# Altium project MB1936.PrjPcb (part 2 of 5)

## Sheet FDCAN.SchDoc: FDCAN
size A4; Date: Not used; ApprovedBy: Not used; CheckedBy: Not used; Author: Not used; CompanyName: STMicroelectronics; DrawnBy: Not used; Engineer: Not used; Organization: Not used; Address1: Not used; Address2: Not used; Address3: Not used; Address4: Not used; DocumentNumber: Not used; Revision: Not used; SheetNumber: 10; SheetTotal: 18
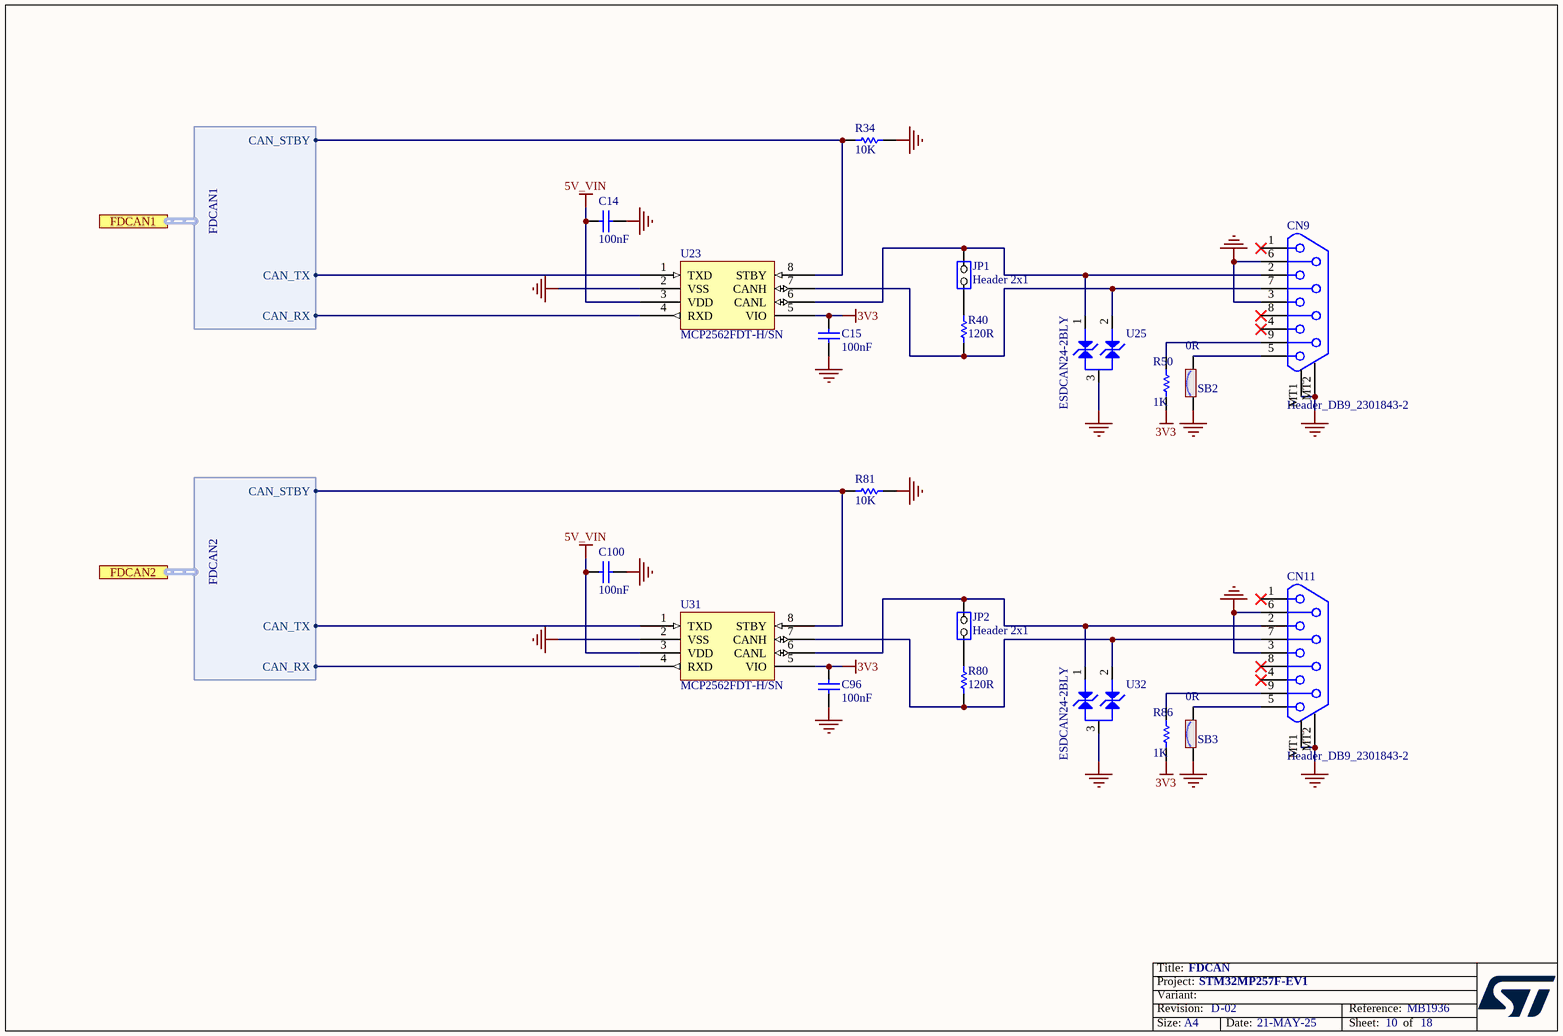
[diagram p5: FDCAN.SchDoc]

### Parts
C14  value 100nF  [C0402]  (hidden comment: Capacitor)
C15  value 100nF  [C0402]  (hidden comment: Capacitor)
C96  value 100nF  [C0402]  (hidden comment: Capacitor)
C100  value 100nF  [C0402]  (hidden comment: Capacitor)
CN9  value Header_DB9_2301843-2  [CON_DB9-MALE_TYCO_2301843-2]  (hidden comment: DB9_Header_male_2301843-2)
CN11  value Header_DB9_2301843-2  [CON_DB9-MALE_TYCO_2301843-2]  (hidden comment: DB9_Header_male_2301843-2)
JP1  value Header 2x1  [CON_SAMTEC_TSW-102-07-G-S]  (hidden comment: Jumper_Header 2x1)
JP2  value Header 2x1  [CON_SAMTEC_TSW-102-07-G-S]  (hidden comment: Jumper_Header 2x1)
R34  value 10K  [R0402]  (hidden comment: Resistor)
R40  value 120R  [R0402]  (hidden comment: Resistor)
R50  value 1K  [R0402]  (hidden comment: Resistor)
R80  value 120R  [R0402]  (hidden comment: Resistor)
R81  value 10K  [R0402]  (hidden comment: Resistor)
R86  value 1K  [R0402]  (hidden comment: Resistor)
SB2  value 0R  [SOLDER-BRIDGE_R0402-0R]  (hidden comment: SB_ON)
SB3  value 0R  [SOLDER-BRIDGE_R0402-0R]  (hidden comment: SB_ON)
U23  value MCP2562FDT-H/SN  [ICC_SO8_5X4_P127]  (hidden comment: MCP2562FD)
U25  value ESDCAN24-2BLY  [ESD_SOT23]  (hidden comment: ESD-TRANSIL-DUAL-BIDIR)
U31  value MCP2562FDT-H/SN  [ICC_SO8_5X4_P127]  (hidden comment: MCP2562FD)
U32  value ESDCAN24-2BLY  [ESD_SOT23]  (hidden comment: ESD-TRANSIL-DUAL-BIDIR)

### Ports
FDCAN1 (harness FDCAN1), FDCAN2 (harness FDCAN2)

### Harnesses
FDCAN1: CAN_TX, CAN_RX, CAN_STBY
FDCAN2: CAN_TX, CAN_RX, CAN_STBY

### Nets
3V3: C15.2 C96.2 R50.1 R86.1 U23.5(VIO) U31.5(VIO)
5V_VIN: C14.1 C100.1 U23.3(VDD) U31.3(VDD)
GND: C14.2 C15.1 C96.1 C100.2 CN9.3 CN9.6 CN9.MT1 CN9.MT2 CN11.3 CN11.6 CN11.MT1 CN11.MT2 R34.2 R81.2 SB2.1 SB3.1 U23.2(VSS) U25.3 U31.2(VSS) U32.3
FDCAN1.RX: U23.4(RXD) ; port FDCAN1.CAN_RX
FDCAN1.STBY: R34.1 U23.8(STBY) ; port FDCAN1.CAN_STBY
FDCAN1.TX: U23.1(TXD) ; port FDCAN1.CAN_TX
FDCAN3.RX: U31.4(RXD) ; port FDCAN2.CAN_RX
FDCAN3.STBY: R81.1 U31.8(STBY) ; port FDCAN2.CAN_STBY
FDCAN3.TX: U31.1(TXD) ; port FDCAN2.CAN_TX
NetCN9_2: CN9.2 JP1.2(NO) U23.6(CANL) U25.1
NetCN9_5: CN9.5 SB2.2
NetCN9_7: CN9.7 R40.1 U23.7(CANH) U25.2
NetCN9_9: CN9.9 R50.2
NetCN11_2: CN11.2 JP2.2(NO) U31.6(CANL) U32.1
NetCN11_5: CN11.5 SB3.2
NetCN11_7: CN11.7 R80.1 U31.7(CANH) U32.2
NetCN11_9: CN11.9 R86.2
NetJP1_1: JP1.1(COMMON) R40.2
NetJP2_1: JP2.1(COMMON) R80.2

Not connected (* = marked no-connect by the designer): CN9 1* 4* 8*; CN11 1* 4* 8*

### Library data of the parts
C14 C15 C96 C100 = MCD-00006: Capacitor, MLCC, 100nF, 16V, X7R, +/-10%, 0402, T=0.5mm; Part_Preference: Recommended; Manufacturer: YAGEO; Manufacturer_Part_Number: CC0402KRX7R7BB104; Partial_Alternate_Internal_Part_Number: MCD-03299; Order_Code_RS: 9402047; Component_Country_Of_Origin: China; ShowFields: YES; ID: 2474
CN9 CN11 = MCD-01978: Connector_DB9-Male, 9pins, 1.39mm, RA, TH, T= 13.575mm/3.8mm; Part_Preference: Recommended; Manufacturer: TE CONNECTIVITY; Partial_Alternate_Internal_Part_Number: MCD-04464; Component_Country_Of_Origin: China; ShowFields: YES; ID: 4078
JP1 JP2 = MCD-00045: Header, 2x1, 2,54mm, VR, TH, Height 5.84mm/2.54mm; Part_Type: Connector; Manufacturer_Part_Number: TSW-102-07-G-S; Manufacturer: SAMTEC; Alternate_Manufacturer_Part_Number: 313102S111116;313102S111116; Alternate_Manufacturer: JIUBABA; LIANYI; Alternate_Internal_Part_Number: MCD-02390; Part_Preference: Recommended; Partial_Alternate_Internal_Part_Number: MCD-02957, MCD-03720, MCD-03979, MCD-04249; Provided_By: SUBCO; Component_Country_Of_Origin: China, Costa Rica, Malaysia, USA, Vietnam; ID: 2545; Order_Code_RS: 2505044; ShowFields: YES
R34 R81 = MCD-00053: Resistor,10K,0402,1%,1/16W; Manufacturer_Part_Number: RC0402FR-0710KL; Manufacturer: YAGEO; BMS_Part_Number: 9131590; Part_Preference: Recommended; Provided_By: SUBCO; Component_Country_Of_Origin: China; ID: 2539; Order_Code_RS: 9239359; ShowFields: YES
R40 R80 = MCD-00194: Resistor, 120R, 0402, +/-1%, 1/16W; Part_Preference: Recommended; Manufacturer: YAGEO; Manufacturer_Part_Number: RC0402FR-07120RL; Component_Country_Of_Origin: China; ShowFields: YES; ID: 2674
R50 R86 = MCD-00061: Resistor,1K,0402,1%,1/16W; Manufacturer_Part_Number: RC0402FR-071KL; Manufacturer: YAGEO; Part_Preference: Recommended; Provided_By: SUBCO; Component_Country_Of_Origin: China; ID: 2532; Order_Code_RS: 9239235; ShowFields: YES
SB2 SB3 = MCD-01618: Solder Bridge 0402 ON; Part_Type: Resistor; Manufacturer_Part_Number: RC0402JR-070RL; Manufacturer: YAGEO; Part_Preference: Recommended; Provided_By: SUBCO; Component_Country_Of_Origin: China; ID: 3718; Order_Code_RS: 618-5804; ShowFields: YES
U23 U31 = MCD-00129: High-Speed CAN Flexible Data Rate Transceiver; Part_Type: IC; Manufacturer: MICROCHIP; Part_Preference: Recommended; Provided_By: SUBCO; Component_Country_Of_Origin: Unknown; ID: 2737; ShowFields: YES
U25 U32 = MCD-00143: Automotive dual-line Transil. ESD CAN; Part_Type: Diode; Manufacturer: STMICROELECTRONICS; BMS_Part_Number: 9179002; Manufacturer_HQ_COO: EU; Part_Preference: Recommended; Provided_By: SUBCO with ST control; Component_Country_Of_Origin: China; ID: 2726; Order_Code_RS: 165-5883; ShowFields: YES

## Sheet Ethernet1.SchDoc: ETHERNET 1
size A3; Date: Not used; ApprovedBy: Not used; CheckedBy: Not used; Author: Not used; CompanyName: STMicroelectronics; DrawnBy: Not used; Engineer: Not used; Organization: Not used; Address1: Not used; Address2: Not used; Address3: Not used; Address4: Not used; DocumentNumber: Not used; Revision: Not used; SheetNumber: 7; SheetTotal: 18
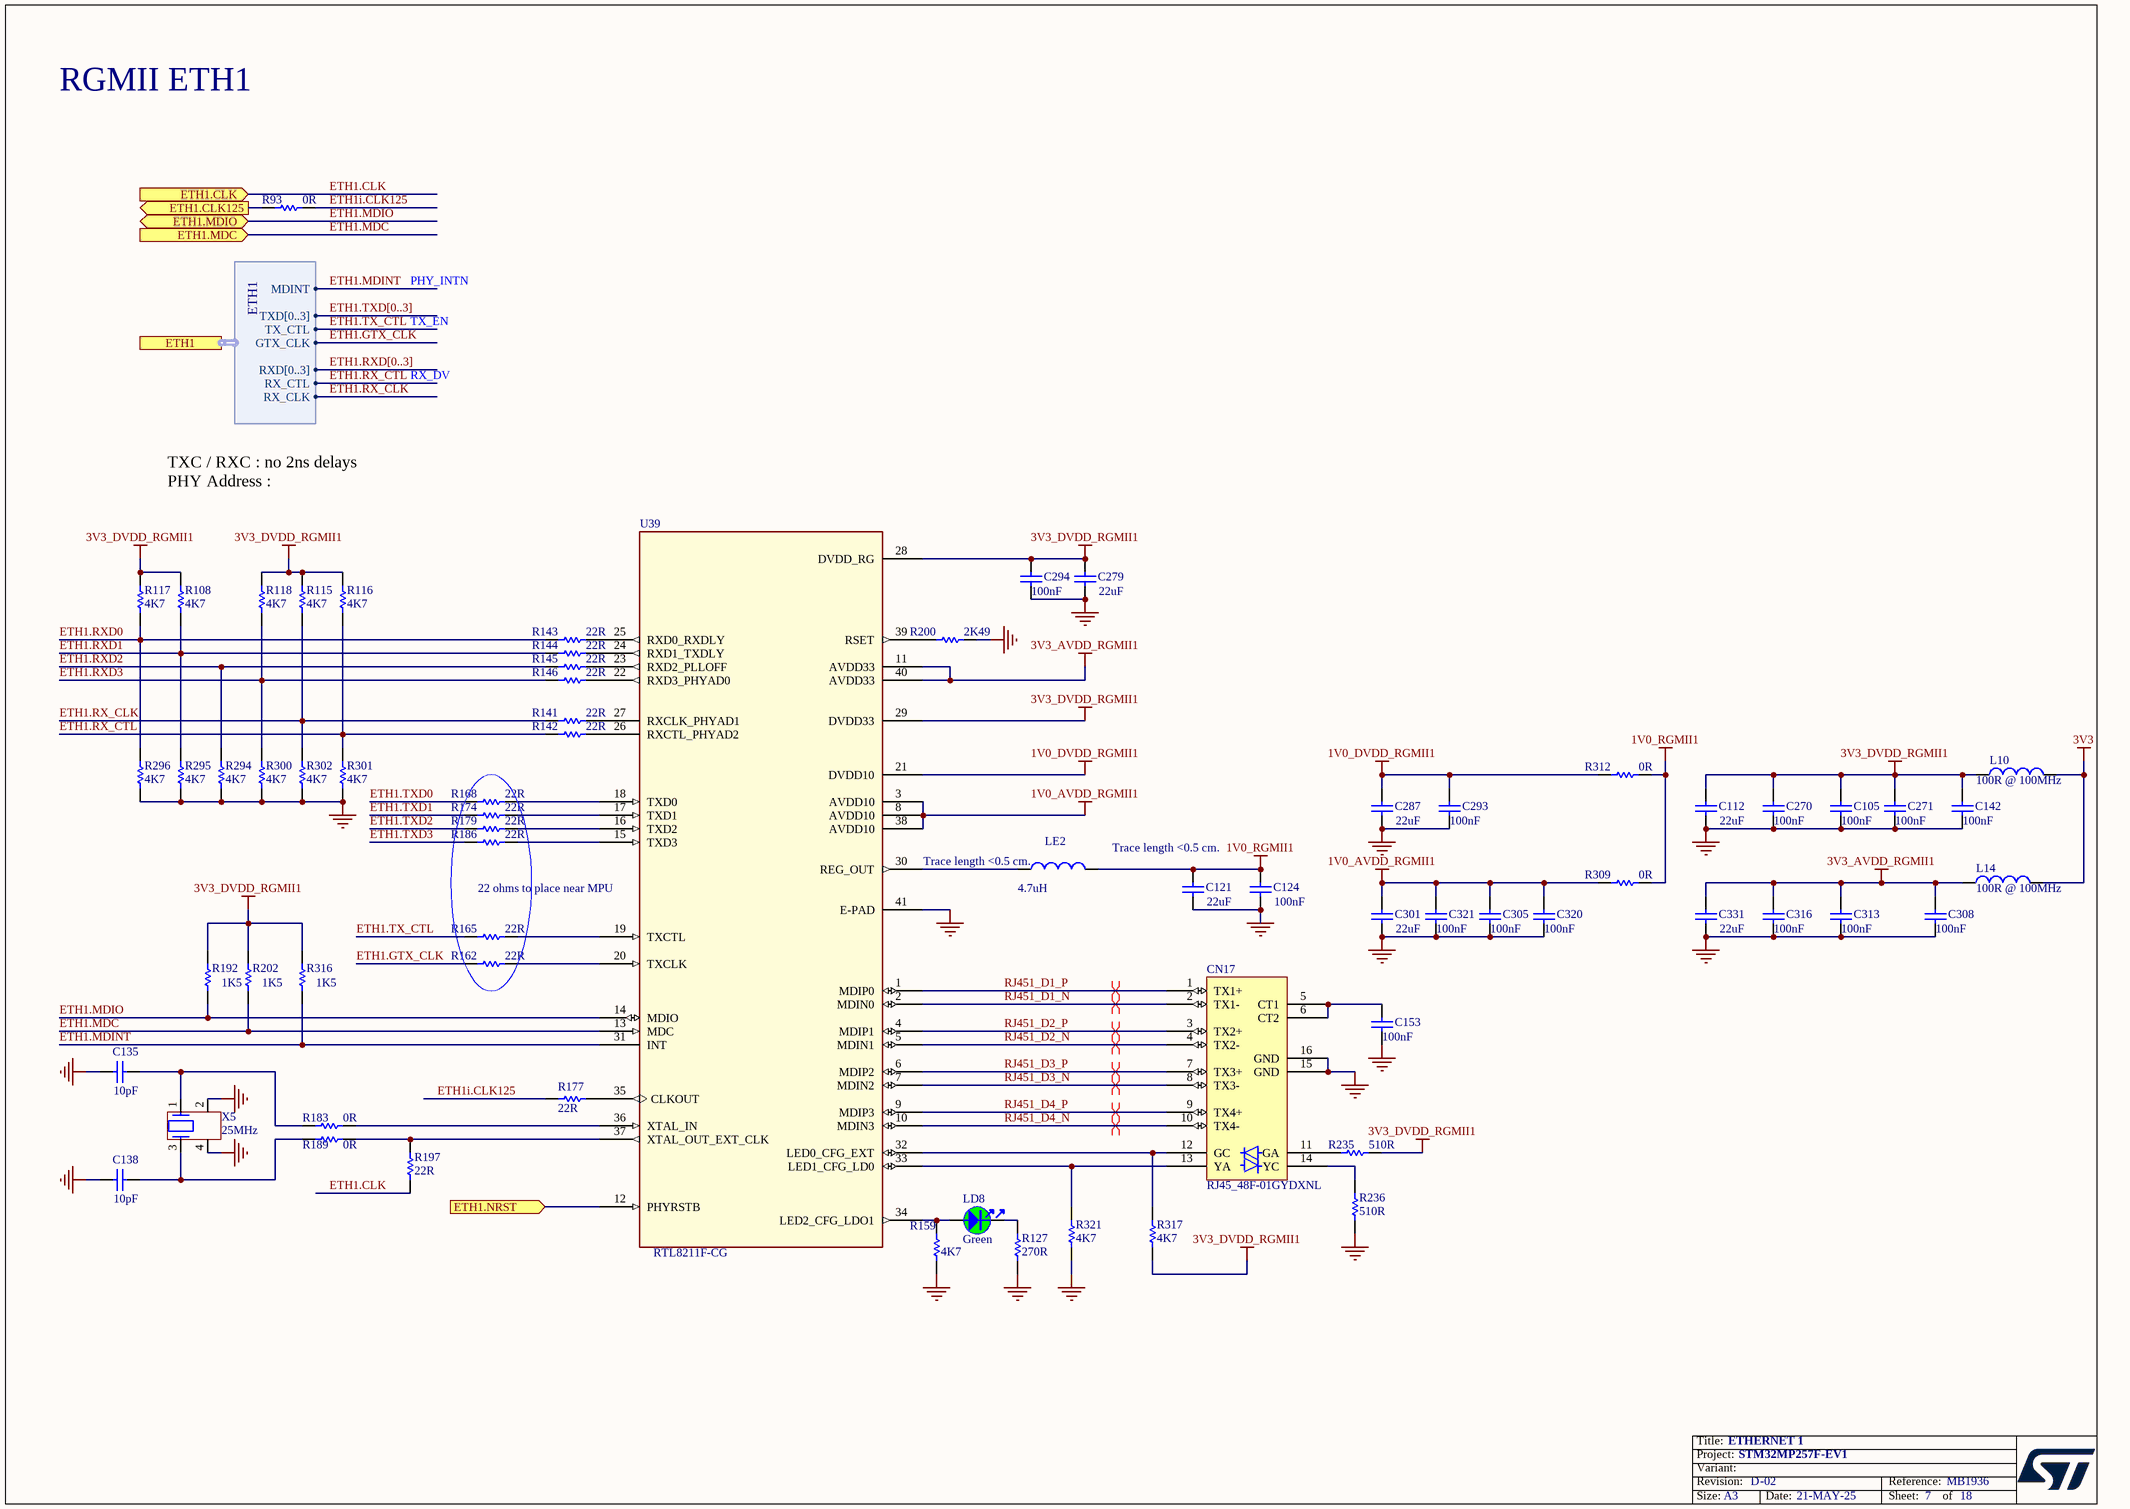
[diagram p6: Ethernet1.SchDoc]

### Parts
C105  value 100nF  [C0402]
C112  value 22uF  [C0603]
C121  value 22uF  [C0603]
C124  value 100nF  [C0402]
C135  value 10pF  [C0402]
C138  value 10pF  [C0402]
C142  value 100nF  [C0402]
C153  value 100nF  [C0402]
C270  value 100nF  [C0402]
C271  value 100nF  [C0402]
C279  value 22uF  [C0603]
C287  value 22uF  [C0603]
C293  value 100nF  [C0402]
C294  value 100nF  [C0402]
C301  value 22uF  [C0603]
C305  value 100nF  [C0402]
C308  value 100nF  [C0402]
C313  value 100nF  [C0402]
C316  value 100nF  [C0402]
C320  value 100nF  [C0402]
C321  value 100nF  [C0402]
C331  value 22uF  [C0603]
CN17  value RJ45_48F-01GYDXNL  [CON_RJ45_YD_48F-01GYDXNL_LED-P]  (hidden comment: ​New part for use of led pulled down on pin 13/14 , schematic more lisible.)
L10  value 100R @ 100MHz  [FIL_0603_H0P65]
L14  value 100R @ 100MHz  [FIL_0603_H0P65]
LD8  value Green  [LED_0603_OSRAM_LG-Q396-PS-35_GREEN_1A2K_H0P4]  (hidden comment: LED_green)
LE2  value 4.7uH  [L1210_LQH]
R93  value 0R  [R0402]
R108  value 4K7  [R0402]
R115  value 4K7  [R0402]
R116  value 4K7  [R0402]
R117  value 4K7  [R0402]
R118  value 4K7  [R0402]
R127  value 270R  [R0402]  (hidden comment: Resistor)
R141  value 22R  [R0201_H0P23]  (hidden comment: Resistor)
R142  value 22R  [R0201_H0P23]  (hidden comment: Resistor)
R143  value 22R  [R0201_H0P23]  (hidden comment: Resistor)
R144  value 22R  [R0201_H0P23]  (hidden comment: Resistor)
R145  value 22R  [R0201_H0P23]  (hidden comment: Resistor)
R146  value 22R  [R0201_H0P23]  (hidden comment: Resistor)
R159  value 4K7  [R0402]
R162  value 22R  [R0201_H0P23]  (hidden comment: Resistor)
R165  value 22R  [R0201_H0P23]  (hidden comment: Resistor)
R168  value 22R  [R0201_H0P23]  (hidden comment: Resistor)
R174  value 22R  [R0201_H0P23]  (hidden comment: Resistor)
R177  value 22R  [R0201_H0P23]  (hidden comment: Resistor)
R179  value 22R  [R0201_H0P23]  (hidden comment: Resistor)
R183  value 0R  [R0402]
R186  value 22R  [R0201_H0P23]  (hidden comment: Resistor)
R189  value 0R  [R0402]
R192  value 1K5  [R0402]
R197  value 22R  [R0201_H0P23]  (hidden comment: Resistor)
R200  value 2K49  [R0402]
R202  value 1K5  [R0402]
R235  value 510R  [R0402]
R236  value 510R  [R0402]
R294  value 4K7  [R0402]
R295  value 4K7  [R0402]
R296  value 4K7  [R0402]
R300  value 4K7  [R0402]
R301  value 4K7  [R0402]
R302  value 4K7  [R0402]
R309  value 0R  [R0603]
R312  value 0R  [R0603]
R316  value 1K5  [R0402]
R317  value 4K7  [R0402]
R321  value 4K7  [R0402]
U39  RTL8211F-CG  [ICC_QFN40-EPAD_5X5_P040]
X5  value 25MHz  [CRY_NX3225HA_4P]  (hidden comment: XTAL_4_PINS)

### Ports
ETH1 (harness ETH1), ETH1.CLK125 (out), ETH1.CLK (in), ETH1.MDC (in), ETH1.MDIO (bidir), ETH1.NRST (in)

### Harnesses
ETH1: MDINT, TXD[0..3], RX_CLK, GTX_CLK, TX_CTL, RXD[0..3], RX_CTL

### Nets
1V0_AVDD_RGMII1: C301.2 C305.2 C320.2 C321.2 R309.1 U39.3(AVDD10) U39.8(AVDD10) U39.38(AVDD10)
1V0_DVDD_RGMII1: C287.2 C293.2 R312.1 U39.21(DVDD10)
1V0_RGMII1: C121.2 C124.2 LE2.2 R309.2 R312.2
3V3: L10.2 L14.2
3V3_AVDD_RGMII1: C308.2 C313.2 C316.2 C331.2 L14.1 U39.11(AVDD33) U39.40(AVDD33)
3V3_DVDD_RGMII1: C105.2 C112.2 C142.2 C270.2 C271.2 C279.1 C294.2 L10.1 R108.2 R115.2 R116.2 R117.2 R118.2 R192.2 R202.2 R235.2 R316.2 R317.1 U39.28(DVDD_RG) U39.29(DVDD33)
GND: C105.1 C112.1 C121.1 C124.1 C135.1 C138.1 C142.1 C153.1 C270.1 C271.1 C279.2 C287.1 C293.1 C294.1 C301.1 C305.1 C308.1 C313.1 C316.1 C320.1 C321.1 C331.1 CN17.15(GND) CN17.16(GND) R127.2 R159.1 R200.2 R236.1 R294.1 R295.1 R296.1 R300.1 R301.1 R302.1 R321.1 U39.41(E-PAD) X5.2 X5.4
ETH1.CLK: R197.1 ; port ETH1.CLK
ETH1.CLK125: R93.1 ; port ETH1.CLK125
ETH1.GTX_CLK: R162.1 ; port ETH1.GTX_CLK
ETH1.MDC: R202.1 U39.13(MDC) ; port ETH1.MDC
ETH1.MDINT: R316.1 U39.31(INT) ; port ETH1.MDINT
ETH1.MDIO: R192.1 U39.14(MDIO) ; port ETH1.MDIO
ETH1.NRST: U39.12(PHYRSTB) ; port ETH1.NRST
ETH1.RX_CLK: R115.1 R141.1 R302.2 ; port ETH1.RX_CLK
ETH1.RX_CTL: R116.1 R142.1 R301.2 ; port ETH1.RX_CTL
ETH1.RXD0: R117.1 R143.1 R296.2
ETH1.RXD1: R108.1 R144.1 R295.2
ETH1.RXD2: R145.1 R294.2
ETH1.RXD3: R118.1 R146.1 R300.2
ETH1.TX_CTL: R165.1 ; port ETH1.TX_CTL
ETH1.TXD0: R168.1
ETH1.TXD1: R174.1
ETH1.TXD2: R179.1
ETH1.TXD3: R186.1
ETH1i.CLK125: R93.2 R177.1
RJ451_D1_N: CN17.2(TX1-) U39.2(MDIN0)
RJ451_D1_P: CN17.1(TX1+) U39.1(MDIP0)
RJ451_D2_N: CN17.4(TX2-) U39.5(MDIN1)
RJ451_D2_P: CN17.3(TX2+) U39.4(MDIP1)
RJ451_D3_N: CN17.8(TX3-) U39.7(MDIN2)
RJ451_D3_P: CN17.7(TX3+) U39.6(MDIP2)
RJ451_D4_N: CN17.10(TX4-) U39.10(MDIN3)
RJ451_D4_P: CN17.9(TX4+) U39.9(MDIP3)
NetC135_2: C135.2 R183.1 X5.1
NetC138_2: C138.2 R189.1 X5.3
NetC153_2: C153.2 CN17.5(CT1) CN17.6(CT2)
NetCN17_11: CN17.11(GA) R235.1
NetCN17_12: CN17.12(GC) R317.2 U39.32(LED0_CFG_EXT)
NetCN17_13: CN17.13(YA) R321.2 U39.33(LED1_CFG_LD0)
NetCN17_14: CN17.14(YC) R236.2
NetLD8_1: LD8.1 R159.2 U39.34(LED2_CFG_LDO1)
NetLD8_2: LD8.2 R127.1
NetLE2_1: LE2.1 U39.30(REG_OUT)
NetR141_2: R141.2 U39.27(RXCLK_PHYAD1)
NetR142_2: R142.2 U39.26(RXCTL_PHYAD2)
NetR143_2: R143.2 U39.25(RXD0_RXDLY)
NetR144_2: R144.2 U39.24(RXD1_TXDLY)
NetR145_2: R145.2 U39.23(RXD2_PLLOFF)
NetR146_2: R146.2 U39.22(RXD3_PHYAD0)
NetR162_2: R162.2 U39.20(TXCLK)
NetR165_2: R165.2 U39.19(TXCTL)
NetR168_2: R168.2 U39.18(TXD0)
NetR174_2: R174.2 U39.17(TXD1)
NetR177_2: R177.2 U39.35(CLKOUT)
NetR179_2: R179.2 U39.16(TXD2)
NetR183_2: R183.2 U39.36(XTAL_IN)
NetR186_2: R186.2 U39.15(TXD3)
NetR189_2: R189.2 R197.2 U39.37(XTAL_OUT_EXT_CLK)
NetR200_1: R200.1 U39.39(RSET)

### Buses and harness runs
bus ETH1.RXD[0..3]
bus ETH1.TXD[0..3]

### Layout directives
differential pair: RJ451_D1_N, RJ451_D1_P, RJ451_D2_N, RJ451_D2_P, RJ451_D3_N, RJ451_D3_P, RJ451_D4_N, RJ451_D4_P

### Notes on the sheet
- RGMII ETH1
- PHY_INTN
- RX_DV
- TX_EN
- TXC / RXC : no 2ns delays
  PHY Address :
  AD[2:0] : 100 (0x04) default
- Trace length <0.5 cm.
- (near U39) 22 ohms to place near MPU
- (near LE2) Trace length <0.5 cm.

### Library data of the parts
C105 C124 C142 C153 C270 C271 C293 C294 C305 C308 C313 C316 C320 C321 = MCD-00006: Capacitor,100nF,16V,X7R,10%,0402; Manufacturer_Part_Number: CC0402KRX7R7BB104; Manufacturer: YAGEO; Alternate_Manufacturer: MURATA; Alternate_Manufacturer_Part_Number: GCM155R71C104KA55D; Part_Preference: Recommended; Partial_Alternate_Internal_Part_Number: MCD-03299; Provided_By: SUBCO; Initial_Board_Reference: mb1274; Order_Code_RS: 9402047; Component_Country_Of_Origin: China; ID: 2474; ShowFields: YES
C112 C121 C279 C287 C301 C331 = MCD-00100: Capacitor,22uF,6V3,X5R,20%,0603; Manufacturer_Part_Number: GRM188R60J226MEA0; Manufacturer: MURATA; Part_Preference: Recommended; Partial_Alternate_Internal_Part_Number: MCD-04184; ECCN_US: EAR99; ECCN_EU: NEC; Provided_By: SUBCO; Initial_Board_Reference: mb1262; Component_Country_Of_Origin: Japan°°; ID: 2766; ShowFields: YES
C135 C138 = MCD-00015: Capacitor,10pF,50V,NPO,5%,0402; Manufacturer_Part_Number: CC0402JRNPO9BN100; Manufacturer: YAGEO; Part_Preference: Recommended; Provided_By: SUBCO; Initial_Board_Reference: mb1274; Order_Code_RS: 3019160RL; Component_Country_Of_Origin: China; ID: 2465; ShowFields: YES
CN17 = MCD-01129: Connector_RJ45, led pull down, T= 13.84mm; Manufacturer_Part_Number: 48F-01GYDXNL; Manufacturer: YUAN DEAN SCIENTIFIC; Part_Preference: Recommended; Partial_Alternate_Internal_Part_Number: MCD-04366; Component_Country_Of_Origin: Unknown; ID: 3367; ShowFields: YES
L10 L14 = MCD-00094: Ferrite bead 100R 2A 0603; Manufacturer_Part_Number: BLM18EG101TN1; Manufacturer: MURATA; Part_Type: Inductor; Part_Preference: Recommended; ECCN_US: EAR99; ECCN_EU: NEC; Provided_By: SUBCO; Initial_Board_Reference: mb1262; Order_Code_RS: 1515714; Component_Country_Of_Origin: Japan°°; ID: 2774; ShowFields: YES
LD8 = MCD-02901: LED, Green, 2V, 20mA, 0603; Part_Type: Display; Part_Preference: Recommended; Manufacturer: EVERLIGHT; Manufacturer_Part_Number: 19-217/G7C-AN1P2/6T; Partial_Alternate_Internal_Part_Number: MCD-02400, MCD-00588; Component_Country_Of_Origin: China; ShowFields: YES; ID: 5017
LE2 = MCD-00048: FIXED IND 4.7UH 1A 180 MOHM 30% SMD; Manufacturer_Part_Number: LQH32PN4R7NN0L; Manufacturer: MURATA; Part_Preference: Recommended; Provided_By: SUBCO; Initial_Board_Reference: mb1274; Order_Code_RS: 2470296; Component_Country_Of_Origin: Japan°°; ID: 2544; ShowFields: YES
R93 R183 R189 = MCD-00052: Resistor,0R,0402,5%,1/16W; Manufacturer_Part_Number: RC0402JR-070RL; Manufacturer: YAGEO; Part_Preference: Recommended; Provided_By: SUBCO; Initial_Board_Reference: mb1274; Order_Code_RS: 9232516RL; Component_Country_Of_Origin: China; ID: 2540; ShowFields: YES
R108 R115-R118 R159 R294-R296 R300-R302 R317 R321 = MCD-00065: Resistor,4K7,0402,1%,1/16W; Manufacturer_Part_Number: RC0402FR-074K7L; Manufacturer: YAGEO; Alternate_Manufacturer_Part_Number: RT0402FRE074K7L; Part_Preference: Recommended; Partial_Alternate_Internal_Part_Number: MCD-03300; Provided_By: SUBCO; Initial_Board_Reference: mb1274; Order_Code_RS: 9239316; Component_Country_Of_Origin: China; ID: 2526; ShowFields: YES
R127 = MCD-00441: Resistor,270R,0402,1%,1/16W; Manufacturer_Part_Number: RC0402FR-07270RL; Manufacturer: YAGEO; Part_Preference: Recommended; Provided_By: SUBCO; ECCN_US: EAR99; ECCN_EU: NEC; Component_Country_Of_Origin: China; ID: 2838; ShowFields: YES
R141-R146 R162 R165 R168 R174 R177 R179 R186 R197 = MCD-02978: Resistor, 22R, 0201, +/-1%, 1/20W; Manufacturer_Part_Number: RC0201FR-0722RL; Manufacturer: YAGEO; Part_Preference: Recommended; Order_Code_RS: 198-7593; ID: 5094; ShowFields: YES; Component_Country_Of_Origin: China
R192 R202 R316 = MCD-00068: Resistor,1K5,0402,1%,1/16W; Manufacturer_Part_Number: RC0402FR-071K5L; Manufacturer: YAGEO; Part_Preference: Recommended; Provided_By: SUBCO; Initial_Board_Reference: mb1274; Order_Code_RS: 9239251; Component_Country_Of_Origin: China; ID: 2524; ShowFields: YES
R200 = MCD-00183: Resistor,2K49,0402,1%,1/16W; Manufacturer_Part_Number: RC0402FR-072K49L; Manufacturer: YAGEO; Part_Preference: Recommended; Provided_By: SUBCO; Component_Country_Of_Origin: China; ID: 2687; ShowFields: YES
R235 R236 = MCD-00064: Resistor,510R,0402,1%,1/16W; Manufacturer_Part_Number: RC0402FR-07510RL; Manufacturer: YAGEO; Part_Preference: Recommended; Provided_By: SUBCO; Initial_Board_Reference: mb1274; Order_Code_RS: 1458804; Component_Country_Of_Origin: China; ID: 2525; ShowFields: YES
R309 R312 = MCD-00056: Resistor,0R,0603,5%,1/10W; Manufacturer_Part_Number: RC0603JR-070RL; Manufacturer: YAGEO; Part_Preference: Recommended; Provided_By: SUBCO; Initial_Board_Reference: mb1274; Order_Code_RS: 9233130RL; Component_Country_Of_Origin: China; ID: 2536; ShowFields: YES
U39 = MCD-01130: 10/100/1000M GIGABIT Ethernet Transceiver, QFN40 , SMPS version; Manufacturer: REALTEK; Part_Type: IC; Part_Preference: Recommended; Provided_By: SUBCO; Initial_Board_Reference: MB1272; Component_Country_Of_Origin: USA; ID: 3370; ShowFields: YES
X5 = MCD-01463: Crystal 25Mhz, 10pF, -+50PPM, SMD; Part_Type: Crystal_Osc; Manufacturer_Part_Number: NX3225GA-25MHZ-EXS00A-CG06750; Manufacturer: NDK; BMS_Part_Number: 9157035; Part_Preference: Recommended; Provided_By: SUBCO; Initial_Board_Reference: MB1272B; Remark: footprint same as CRY_NX3225HA_4P; Component_Country_Of_Origin: China; ID: 3563; ShowFields: YES

## Sheet Ethernet2.SchDoc: ETHERNET 2
size A3; Date: Not used; ApprovedBy: Not used; CheckedBy: Not used; Author: Not used; CompanyName: STMicroelectronics; DrawnBy: Not used; Engineer: Not used; Organization: Not used; Address1: Not used; Address2: Not used; Address3: Not used; Address4: Not used; DocumentNumber: Not used; Revision: Not used; SheetNumber: 8; SheetTotal: 18
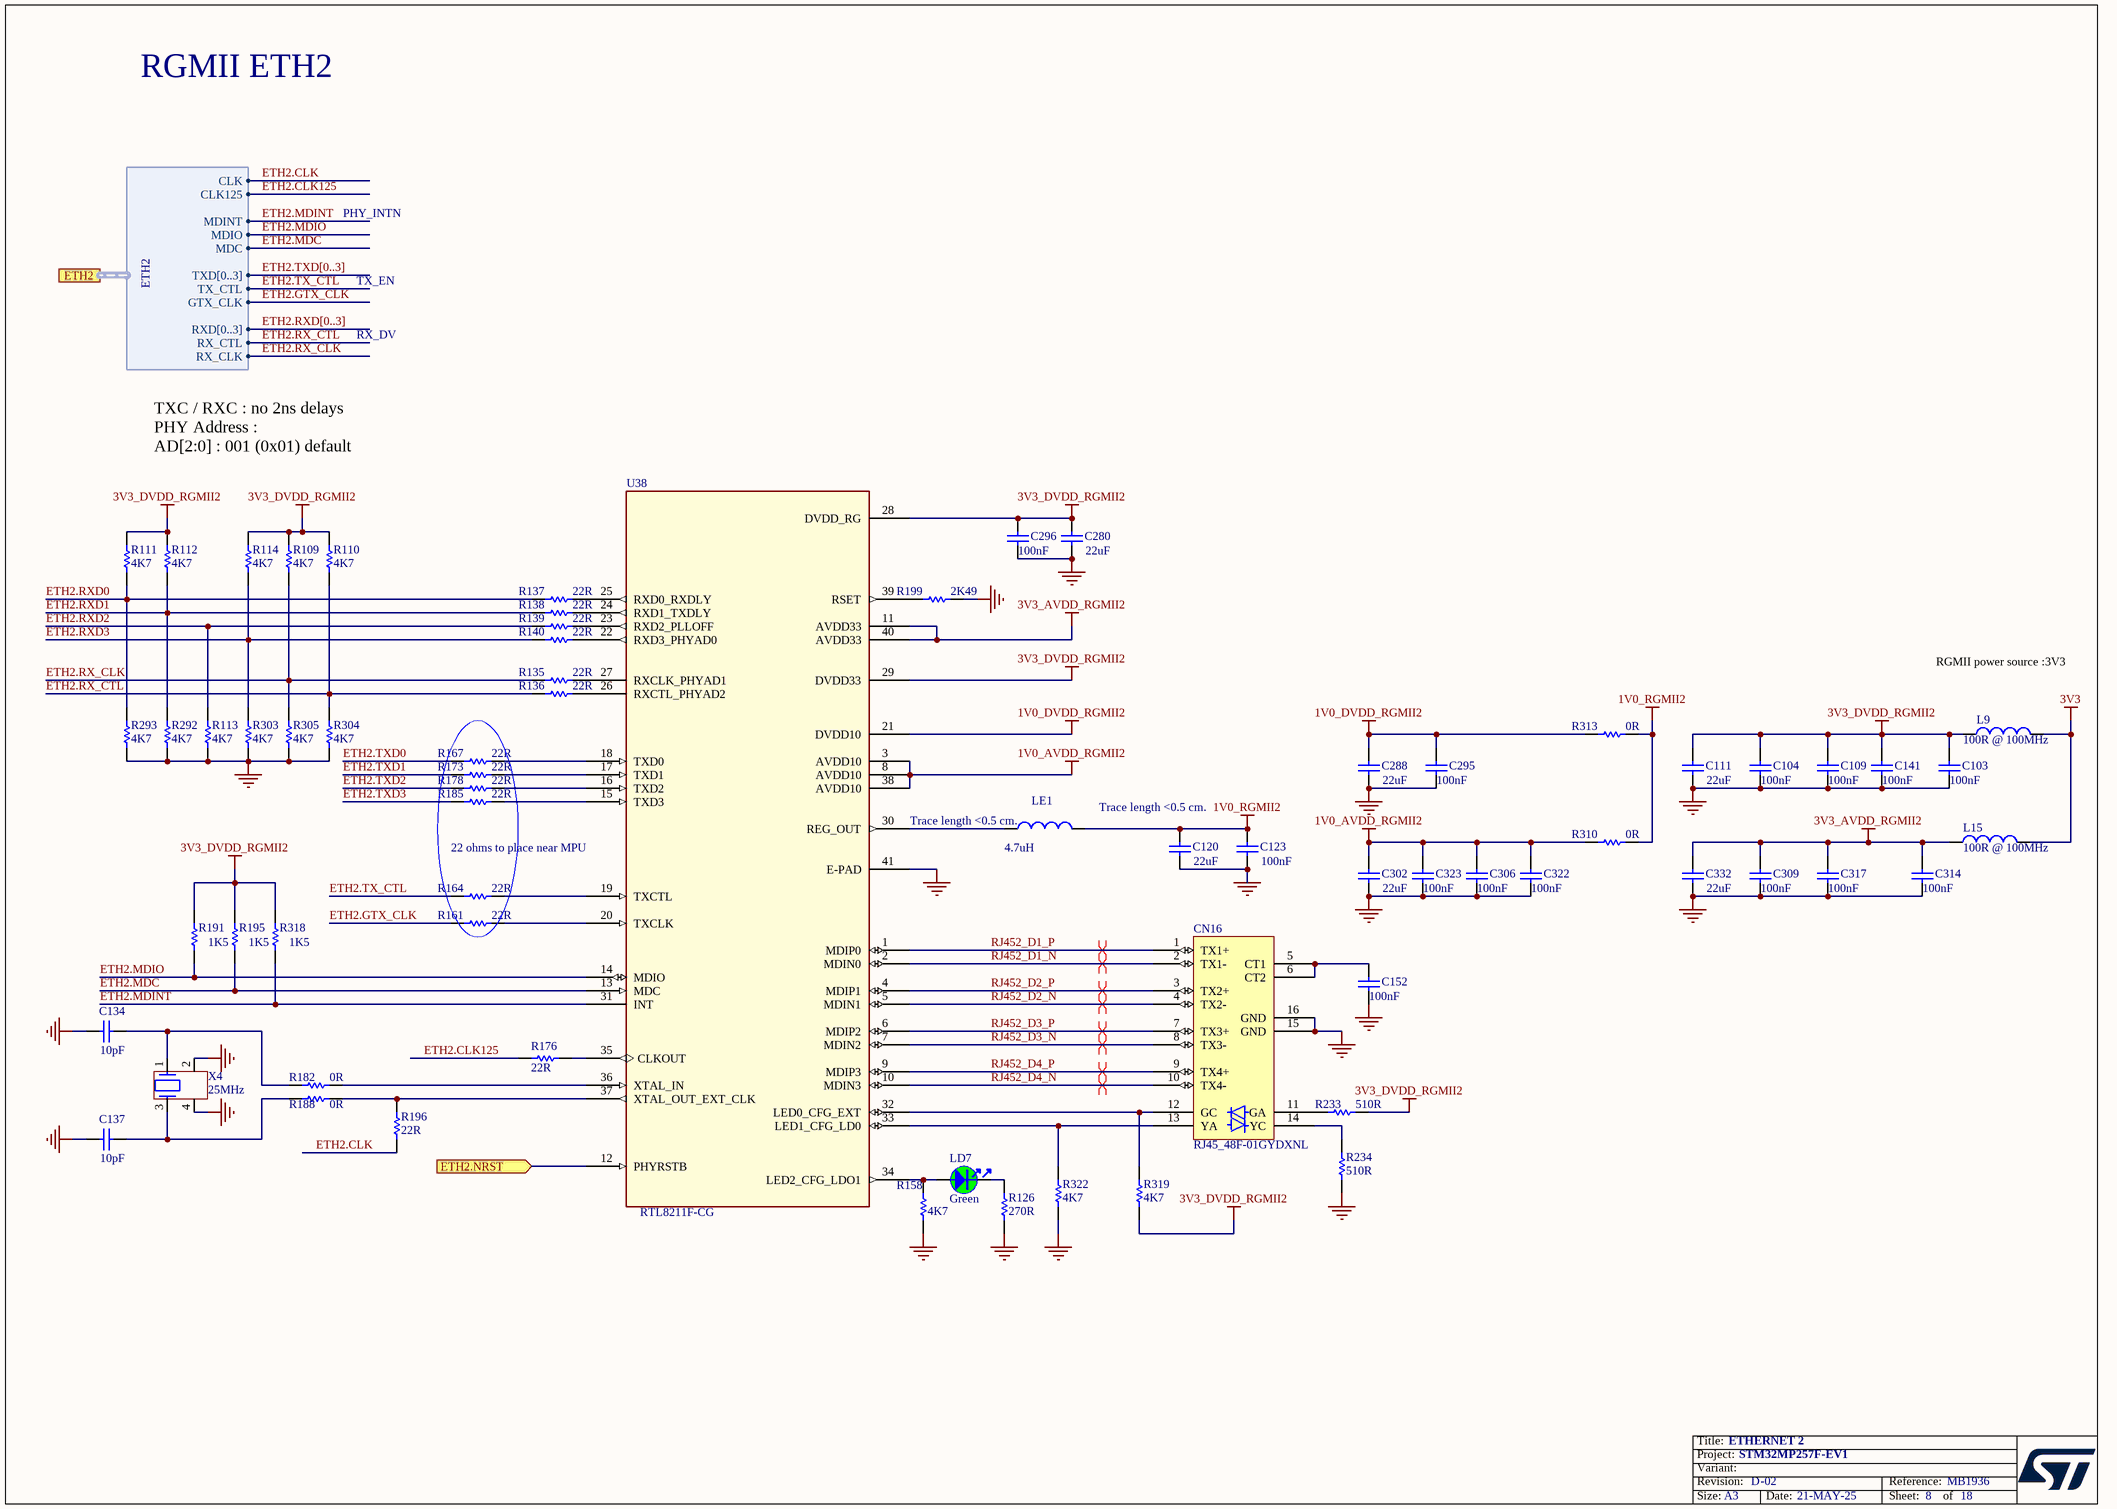
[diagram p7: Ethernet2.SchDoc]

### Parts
C103  value 100nF  [C0402]
C104  value 100nF  [C0402]
C109  value 100nF  [C0402]
C111  value 22uF  [C0603]
C120  value 22uF  [C0603]
C123  value 100nF  [C0402]
C134  value 10pF  [C0402]
C137  value 10pF  [C0402]
C141  value 100nF  [C0402]
C152  value 100nF  [C0402]
C280  value 22uF  [C0603]
C288  value 22uF  [C0603]
C295  value 100nF  [C0402]
C296  value 100nF  [C0402]
C302  value 22uF  [C0603]
C306  value 100nF  [C0402]
C309  value 100nF  [C0402]
C314  value 100nF  [C0402]
C317  value 100nF  [C0402]
C322  value 100nF  [C0402]
C323  value 100nF  [C0402]
C332  value 22uF  [C0603]
CN16  value RJ45_48F-01GYDXNL  [CON_RJ45_YD_48F-01GYDXNL_LED-P]  (hidden comment: ​New part for use of led pulled down on pin 13/14 , schematic more lisible.)
L9  value 100R @ 100MHz  [FIL_0603_H0P65]
L15  value 100R @ 100MHz  [FIL_0603_H0P65]
LD7  value Green  [LED_0603_OSRAM_LG-Q396-PS-35_GREEN_1A2K_H0P4]  (hidden comment: LED_green)
LE1  value 4.7uH  [L1210_LQH]
R109  value 4K7  [R0402]
R110  value 4K7  [R0402]
R111  value 4K7  [R0402]
R112  value 4K7  [R0402]
R113  value 4K7  [R0402]
R114  value 4K7  [R0402]
R126  value 270R  [R0402]  (hidden comment: Resistor)
R135  value 22R  [R0201_H0P23]  (hidden comment: Resistor)
R136  value 22R  [R0201_H0P23]  (hidden comment: Resistor)
R137  value 22R  [R0201_H0P23]  (hidden comment: Resistor)
R138  value 22R  [R0201_H0P23]  (hidden comment: Resistor)
R139  value 22R  [R0201_H0P23]  (hidden comment: Resistor)
R140  value 22R  [R0201_H0P23]  (hidden comment: Resistor)
R158  value 4K7  [R0402]
R161  value 22R  [R0201_H0P23]  (hidden comment: Resistor)
R164  value 22R  [R0201_H0P23]  (hidden comment: Resistor)
R167  value 22R  [R0201_H0P23]  (hidden comment: Resistor)
R173  value 22R  [R0201_H0P23]  (hidden comment: Resistor)
R176  value 22R  [R0201_H0P23]  (hidden comment: Resistor)
R178  value 22R  [R0201_H0P23]  (hidden comment: Resistor)
R182  value 0R  [R0402]
R185  value 22R  [R0201_H0P23]  (hidden comment: Resistor)
R188  value 0R  [R0402]
R191  value 1K5  [R0402]
R195  value 1K5  [R0402]
R196  value 22R  [R0201_H0P23]  (hidden comment: Resistor)
R199  value 2K49  [R0402]
R233  value 510R  [R0402]
R234  value 510R  [R0402]
R292  value 4K7  [R0402]
R293  value 4K7  [R0402]
R303  value 4K7  [R0402]
R304  value 4K7  [R0402]
R305  value 4K7  [R0402]
R310  value 0R  [R0603]
R313  value 0R  [R0603]
R318  value 1K5  [R0402]
R319  value 4K7  [R0402]
R322  value 4K7  [R0402]
U38  RTL8211F-CG  [ICC_QFN40-EPAD_5X5_P040]
X4  value 25MHz  [CRY_NX3225HA_4P]  (hidden comment: XTAL_4_PINS)

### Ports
ETH2 (harness ETH2), ETH2.NRST (in)

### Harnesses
ETH2: MDINT, CLK125, TXD[0..3], MDIO, MDC, RX_CLK, GTX_CLK, TX_CTL, RXD[0..3], RX_CTL, CLK

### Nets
1V0_AVDD_RGMII2: C302.2 C306.2 C322.2 C323.2 R310.1 U38.3(AVDD10) U38.8(AVDD10) U38.38(AVDD10)
1V0_DVDD_RGMII2: C288.2 C295.2 R313.1 U38.21(DVDD10)
1V0_RGMII2: C120.2 C123.2 LE1.2 R310.2 R313.2
3V3: L9.2 L15.2
3V3_AVDD_RGMII2: C309.2 C314.2 C317.2 C332.2 L15.1 U38.11(AVDD33) U38.40(AVDD33)
3V3_DVDD_RGMII2: C103.2 C104.2 C109.2 C111.2 C141.2 C280.1 C296.2 L9.1 R109.2 R110.2 R111.2 R112.2 R114.2 R191.2 R195.2 R233.2 R318.2 R319.1 U38.28(DVDD_RG) U38.29(DVDD33)
GND: C103.1 C104.1 C109.1 C111.1 C120.1 C123.1 C134.1 C137.1 C141.1 C152.1 C280.2 C288.1 C295.1 C296.1 C302.1 C306.1 C309.1 C314.1 C317.1 C322.1 C323.1 C332.1 CN16.15(GND) CN16.16(GND) R113.1 R126.2 R158.1 R199.2 R234.1 R292.1 R293.1 R303.1 R304.1 R305.1 R322.1 U38.41(E-PAD) X4.2 X4.4
ETH2.CLK: R196.1 ; port ETH2.CLK
ETH2.CLK125: R176.1 ; port ETH2.CLK125
ETH2.GTX_CLK: R161.1 ; port ETH2.GTX_CLK
ETH2.MDC: R195.1 U38.13(MDC) ; port ETH2.MDC
ETH2.MDINT: R318.1 U38.31(INT) ; port ETH2.MDINT
ETH2.MDIO: R191.1 U38.14(MDIO) ; port ETH2.MDIO
ETH2.NRST: U38.12(PHYRSTB) ; port ETH2.NRST
ETH2.RX_CLK: R109.1 R135.1 R305.2 ; port ETH2.RX_CLK
ETH2.RX_CTL: R110.1 R136.1 R304.2 ; port ETH2.RX_CTL
ETH2.RXD0: R111.1 R137.1 R293.2
ETH2.RXD1: R112.1 R138.1 R292.2
ETH2.RXD2: R113.2 R139.1
ETH2.RXD3: R114.1 R140.1 R303.2
ETH2.TX_CTL: R164.1 ; port ETH2.TX_CTL
ETH2.TXD0: R167.1
ETH2.TXD1: R173.1
ETH2.TXD2: R178.1
ETH2.TXD3: R185.1
RJ452_D1_N: CN16.2(TX1-) U38.2(MDIN0)
RJ452_D1_P: CN16.1(TX1+) U38.1(MDIP0)
RJ452_D2_N: CN16.4(TX2-) U38.5(MDIN1)
RJ452_D2_P: CN16.3(TX2+) U38.4(MDIP1)
RJ452_D3_N: CN16.8(TX3-) U38.7(MDIN2)
RJ452_D3_P: CN16.7(TX3+) U38.6(MDIP2)
RJ452_D4_N: CN16.10(TX4-) U38.10(MDIN3)
RJ452_D4_P: CN16.9(TX4+) U38.9(MDIP3)
NetC134_2: C134.2 R182.1 X4.1
NetC137_2: C137.2 R188.1 X4.3
NetC152_2: C152.2 CN16.5(CT1) CN16.6(CT2)
NetCN16_11: CN16.11(GA) R233.1
NetCN16_12: CN16.12(GC) R319.2 U38.32(LED0_CFG_EXT)
NetCN16_13: CN16.13(YA) R322.2 U38.33(LED1_CFG_LD0)
NetCN16_14: CN16.14(YC) R234.2
NetLD7_1: LD7.1 R158.2 U38.34(LED2_CFG_LDO1)
NetLD7_2: LD7.2 R126.1
NetLE1_1: LE1.1 U38.30(REG_OUT)
NetR135_2: R135.2 U38.27(RXCLK_PHYAD1)
NetR136_2: R136.2 U38.26(RXCTL_PHYAD2)
NetR137_2: R137.2 U38.25(RXD0_RXDLY)
NetR138_2: R138.2 U38.24(RXD1_TXDLY)
NetR139_2: R139.2 U38.23(RXD2_PLLOFF)
NetR140_2: R140.2 U38.22(RXD3_PHYAD0)
NetR161_2: R161.2 U38.20(TXCLK)
NetR164_2: R164.2 U38.19(TXCTL)
NetR167_2: R167.2 U38.18(TXD0)
NetR173_2: R173.2 U38.17(TXD1)
NetR176_2: R176.2 U38.35(CLKOUT)
NetR178_2: R178.2 U38.16(TXD2)
NetR182_2: R182.2 U38.36(XTAL_IN)
NetR185_2: R185.2 U38.15(TXD3)
NetR188_2: R188.2 R196.2 U38.37(XTAL_OUT_EXT_CLK)
NetR199_1: R199.1 U38.39(RSET)

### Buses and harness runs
bus ETH2.RXD[0..3]
bus ETH2.TXD[0..3]

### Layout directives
differential pair: RJ452_D1_N, RJ452_D1_P, RJ452_D2_N, RJ452_D2_P, RJ452_D3_N, RJ452_D3_P, RJ452_D4_N, RJ452_D4_P

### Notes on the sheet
- RGMII ETH2
- PHY_INTN
- TX_EN
- RX_DV
- TXC / RXC : no 2ns delays
  PHY Address :
  AD[2:0] : 001 (0x01) default
- RGMII power source :3V3
- (near U38) 22 ohms to place near MPU
- (near LE1) Trace length <0.5 cm.
- Trace length <0.5 cm.

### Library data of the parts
C103 C104 C109 C123 C141 C152 C295 C296 C306 C309 C314 C317 C322 C323 = MCD-00006: as C105 on sheet Ethernet1
C111 C120 C280 C288 C302 C332 = MCD-00100: as C112 on sheet Ethernet1
C134 C137 = MCD-00015: as C135 on sheet Ethernet1
CN16 = MCD-01129: as CN17 on sheet Ethernet1
L9 L15 = MCD-00094: as L10 on sheet Ethernet1
LD7 = MCD-02901: as LD8 on sheet Ethernet1
LE1 = MCD-00048: as LE2 on sheet Ethernet1
R109-R114 R158 R292 R293 R303-R305 R319 R322 = MCD-00065: as R108 on sheet Ethernet1
R126 = MCD-00441: as R127 on sheet Ethernet1
R135-R140 R161 R164 R167 R173 R176 R178 R185 R196 = MCD-02978: as R141-R146 on sheet Ethernet1
R182 R188 = MCD-00052: as R93 on sheet Ethernet1
R191 R195 R318 = MCD-00068: as R192 on sheet Ethernet1
R199 = MCD-00183: as R200 on sheet Ethernet1
R233 R234 = MCD-00064: as R235 on sheet Ethernet1
R310 R313 = MCD-00056: as R309 on sheet Ethernet1
U38 = MCD-01130: as U39 on sheet Ethernet1
X4 = MCD-01463: as X5 on sheet Ethernet1

## Sheet Ethernet3.SchDoc: ETHERNET 3
size A3; Date: Not used; ApprovedBy: Not used; CheckedBy: Not used; Author: Not used; CompanyName: STMicroelectronics; DrawnBy: Not used; Engineer: Not used; Organization: Not used; Address1: Not used; Address2: Not used; Address3: Not used; Address4: Not used; DocumentNumber: Not used; Revision: Not used; SheetNumber: 9; SheetTotal: 18
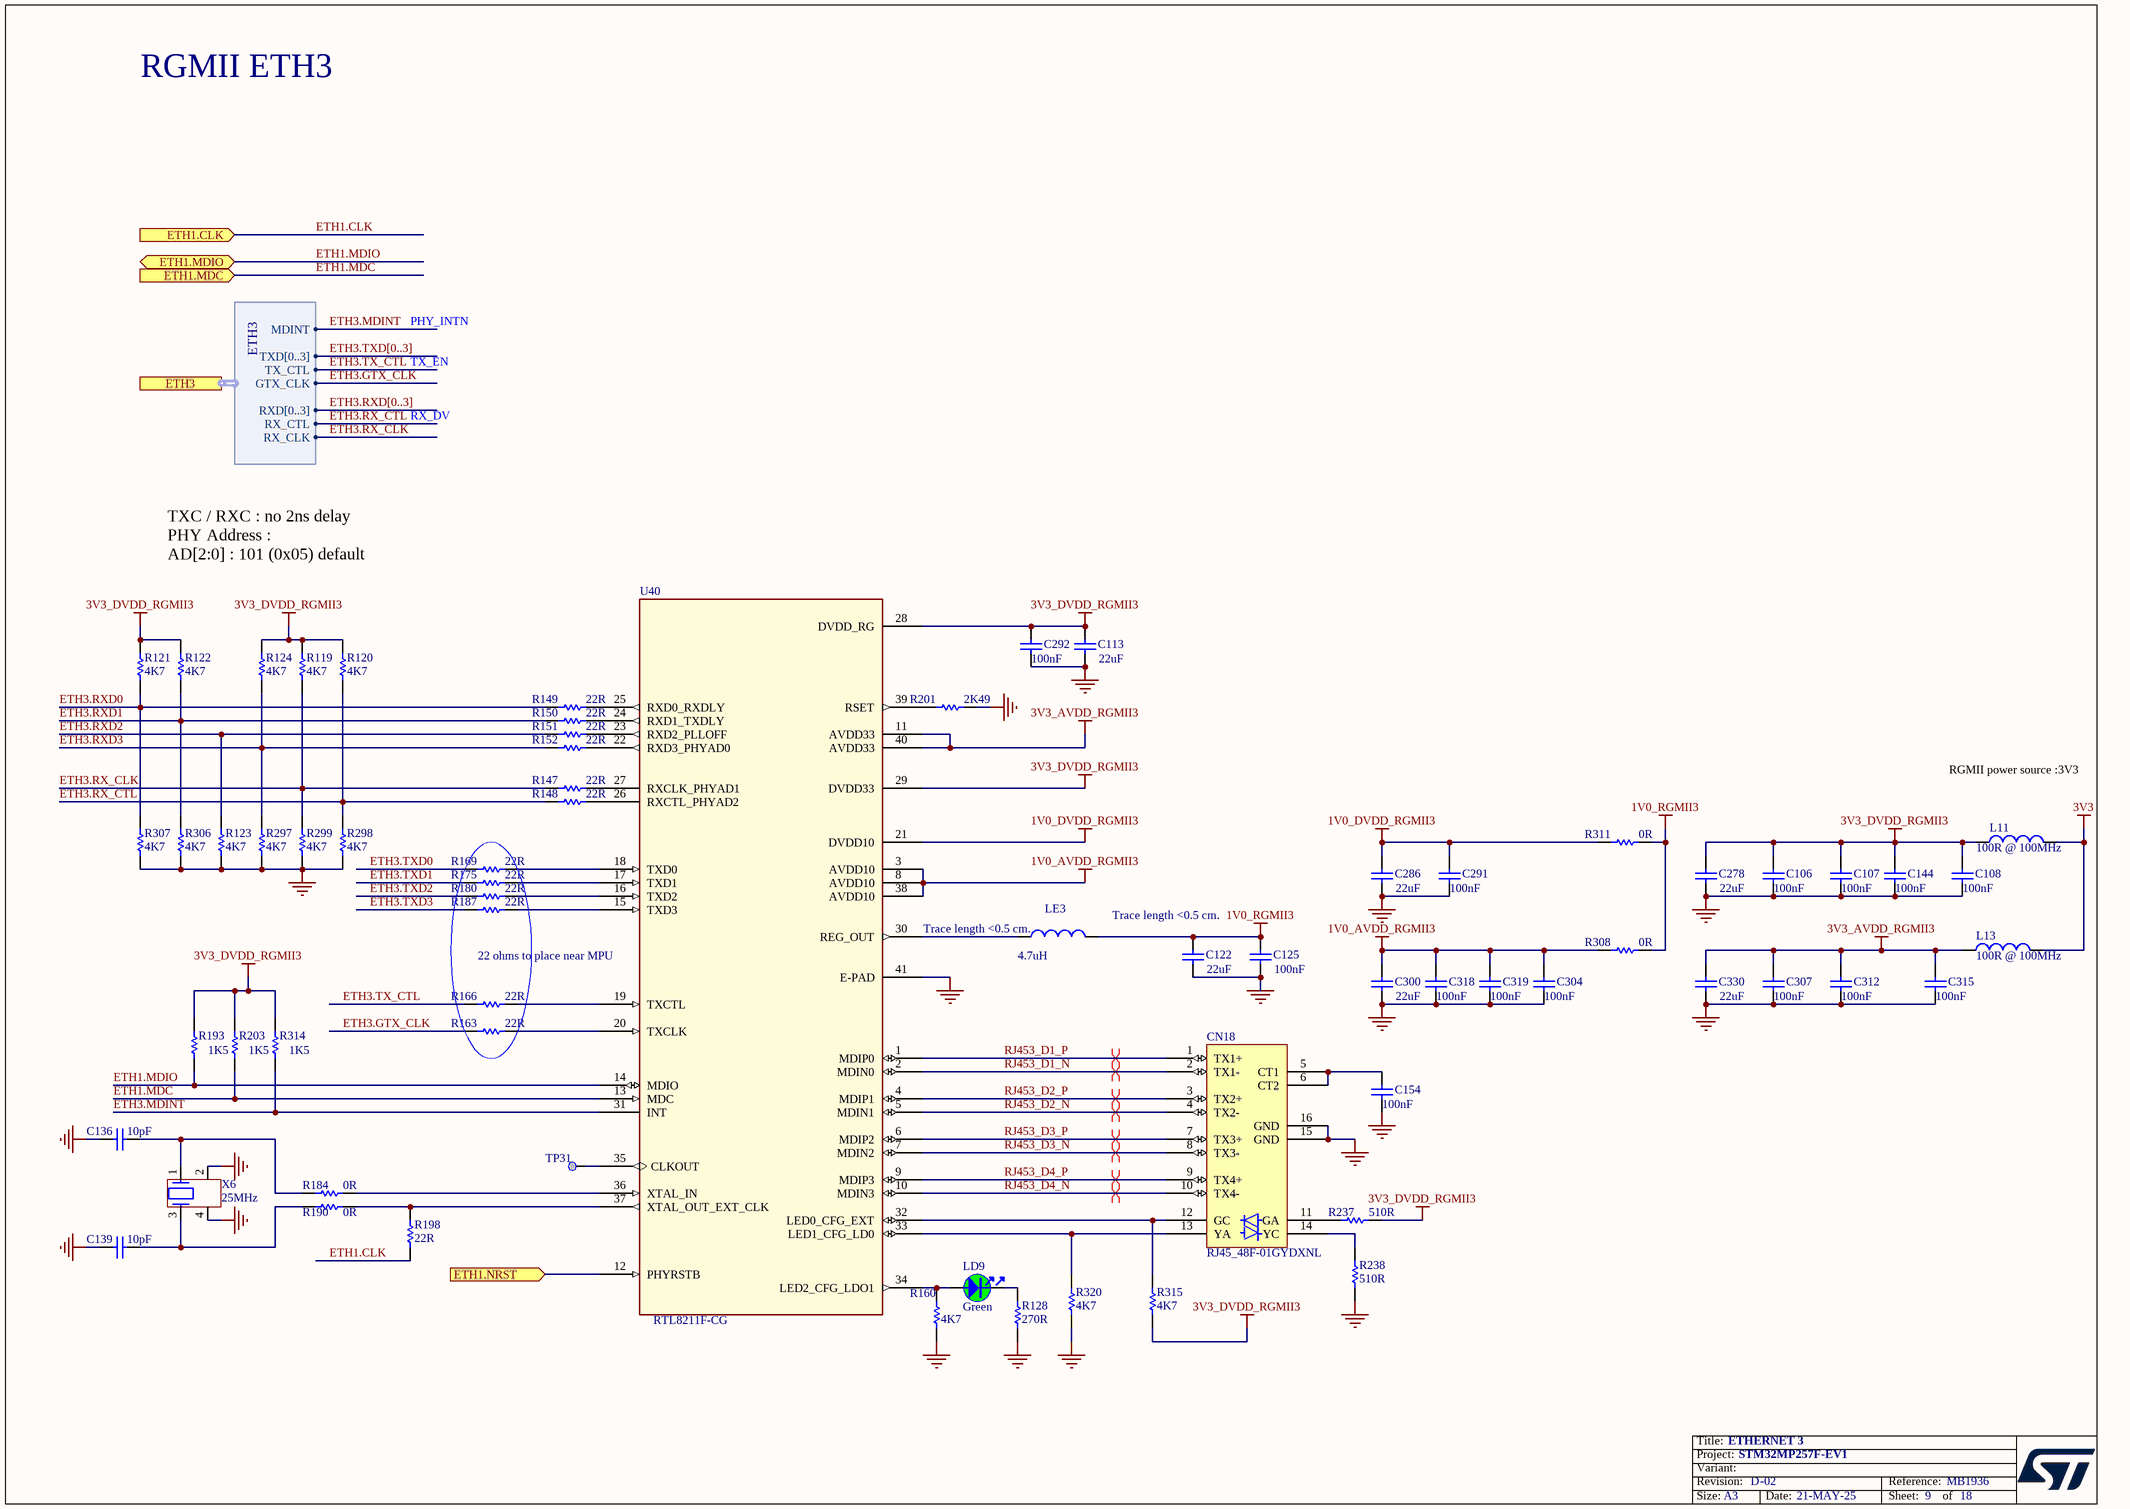
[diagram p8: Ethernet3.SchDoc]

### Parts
C106  value 100nF  [C0402]
C107  value 100nF  [C0402]
C108  value 100nF  [C0402]
C113  value 22uF  [C0603]
C122  value 22uF  [C0603]
C125  value 100nF  [C0402]
C136  value 10pF  [C0402]
C139  value 10pF  [C0402]
C144  value 100nF  [C0402]
C154  value 100nF  [C0402]
C278  value 22uF  [C0603]
C286  value 22uF  [C0603]
C291  value 100nF  [C0402]
C292  value 100nF  [C0402]
C300  value 22uF  [C0603]
C304  value 100nF  [C0402]
C307  value 100nF  [C0402]
C312  value 100nF  [C0402]
C315  value 100nF  [C0402]
C318  value 100nF  [C0402]
C319  value 100nF  [C0402]
C330  value 22uF  [C0603]
CN18  value RJ45_48F-01GYDXNL  [CON_RJ45_YD_48F-01GYDXNL_LED-P]  (hidden comment: ​New part for use of led pulled down on pin 13/14 , schematic more lisible.)
L11  value 100R @ 100MHz  [FIL_0603_H0P65]
L13  value 100R @ 100MHz  [FIL_0603_H0P65]
LD9  value Green  [LED_0603_OSRAM_LG-Q396-PS-35_GREEN_1A2K_H0P4]  (hidden comment: LED_green)
LE3  value 4.7uH  [L1210_LQH]
R119  value 4K7  [R0402]
R120  value 4K7  [R0402]
R121  value 4K7  [R0402]
R122  value 4K7  [R0402]
R123  value 4K7  [R0402]
R124  value 4K7  [R0402]
R128  value 270R  [R0402]  (hidden comment: Resistor)
R147  value 22R  [R0201_H0P23]  (hidden comment: Resistor)
R148  value 22R  [R0201_H0P23]  (hidden comment: Resistor)
R149  value 22R  [R0201_H0P23]  (hidden comment: Resistor)
R150  value 22R  [R0201_H0P23]  (hidden comment: Resistor)
R151  value 22R  [R0201_H0P23]  (hidden comment: Resistor)
R152  value 22R  [R0201_H0P23]  (hidden comment: Resistor)
R160  value 4K7  [R0402]
R163  value 22R  [R0201_H0P23]  (hidden comment: Resistor)
R166  value 22R  [R0201_H0P23]  (hidden comment: Resistor)
R169  value 22R  [R0201_H0P23]  (hidden comment: Resistor)
R175  value 22R  [R0201_H0P23]  (hidden comment: Resistor)
R180  value 22R  [R0201_H0P23]  (hidden comment: Resistor)
R184  value 0R  [R0402]
R187  value 22R  [R0201_H0P23]  (hidden comment: Resistor)
R190  value 0R  [R0402]
R193  value 1K5  [R0402]
R198  value 22R  [R0201_H0P23]  (hidden comment: Resistor)
R201  value 2K49  [R0402]
R203  value 1K5  [R0402]
R237  value 510R  [R0402]
R238  value 510R  [R0402]
R297  value 4K7  [R0402]
R298  value 4K7  [R0402]
R299  value 4K7  [R0402]
R306  value 4K7  [R0402]
R307  value 4K7  [R0402]
R308  value 0R  [R0603]
R311  value 0R  [R0603]
R314  value 1K5  [R0402]
R315  value 4K7  [R0402]
R320  value 4K7  [R0402]
TP31  Test Point  [TP_SMD_1MM]  (value not drawn)  (no BOM)
U40  RTL8211F-CG  [ICC_QFN40-EPAD_5X5_P040]
X6  value 25MHz  [CRY_NX3225HA_4P]  (hidden comment: XTAL_4_PINS)

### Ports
ETH1.CLK (in), ETH1.MDC (in), ETH1.MDIO (bidir), ETH1.NRST (in), ETH3 (harness ETH3)

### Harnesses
ETH3: MDINT, TXD[0..3], RX_CLK, GTX_CLK, TX_CTL, RXD[0..3], RX_CTL

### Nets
1V0_AVDD_RGMII3: C300.2 C304.2 C318.2 C319.2 R308.1 U40.3(AVDD10) U40.8(AVDD10) U40.38(AVDD10)
1V0_DVDD_RGMII3: C286.2 C291.2 R311.1 U40.21(DVDD10)
1V0_RGMII3: C122.2 C125.2 LE3.2 R308.2 R311.2
3V3: L11.2 L13.2
3V3_AVDD_RGMII3: C307.2 C312.2 C315.2 C330.2 L13.1 U40.11(AVDD33) U40.40(AVDD33)
3V3_DVDD_RGMII3: C106.2 C107.2 C108.2 C113.1 C144.2 C278.2 C292.2 L11.1 R119.2 R120.2 R121.2 R122.2 R124.2 R193.2 R203.2 R237.2 R314.2 R315.1 U40.28(DVDD_RG) U40.29(DVDD33)
GND: C106.1 C107.1 C108.1 C113.2 C122.1 C125.1 C136.1 C139.1 C144.1 C154.1 C278.1 C286.1 C291.1 C292.1 C300.1 C304.1 C307.1 C312.1 C315.1 C318.1 C319.1 C330.1 CN18.15(GND) CN18.16(GND) R123.1 R128.2 R160.1 R201.2 R238.1 R297.1 R298.1 R299.1 R306.1 R307.1 R320.1 U40.41(E-PAD) X6.2 X6.4
ETH1.CLK: R198.1 ; port ETH1.CLK
ETH1.MDC: R203.1 U40.13(MDC) ; port ETH1.MDC
ETH1.MDIO: R193.1 U40.14(MDIO) ; port ETH1.MDIO
ETH1.NRST: U40.12(PHYRSTB) ; port ETH1.NRST
ETH3.GTX_CLK: R163.1 ; port ETH3.GTX_CLK
ETH3.MDINT: R314.1 U40.31(INT) ; port ETH3.MDINT
ETH3.RX_CLK: R119.1 R147.1 R299.2 ; port ETH3.RX_CLK
ETH3.RX_CTL: R120.1 R148.1 R298.2 ; port ETH3.RX_CTL
ETH3.RXD0: R121.1 R149.1 R307.2
ETH3.RXD1: R122.1 R150.1 R306.2
ETH3.RXD2: R123.2 R151.1
ETH3.RXD3: R124.1 R152.1 R297.2
ETH3.TX_CTL: R166.1 ; port ETH3.TX_CTL
ETH3.TXD0: R169.1
ETH3.TXD1: R175.1
ETH3.TXD2: R180.1
ETH3.TXD3: R187.1
RJ453_D1_N: CN18.2(TX1-) U40.2(MDIN0)
RJ453_D1_P: CN18.1(TX1+) U40.1(MDIP0)
RJ453_D2_N: CN18.4(TX2-) U40.5(MDIN1)
RJ453_D2_P: CN18.3(TX2+) U40.4(MDIP1)
RJ453_D3_N: CN18.8(TX3-) U40.7(MDIN2)
RJ453_D3_P: CN18.7(TX3+) U40.6(MDIP2)
RJ453_D4_N: CN18.10(TX4-) U40.10(MDIN3)
RJ453_D4_P: CN18.9(TX4+) U40.9(MDIP3)
NetC136_2: C136.2 R184.1 X6.1
NetC139_2: C139.2 R190.1 X6.3
NetC154_2: C154.2 CN18.5(CT1) CN18.6(CT2)
NetCN18_11: CN18.11(GA) R237.1
NetCN18_12: CN18.12(GC) R315.2 U40.32(LED0_CFG_EXT)
NetCN18_13: CN18.13(YA) R320.2 U40.33(LED1_CFG_LD0)
NetCN18_14: CN18.14(YC) R238.2
NetLD9_1: LD9.1 R160.2 U40.34(LED2_CFG_LDO1)
NetLD9_2: LD9.2 R128.1
NetLE3_1: LE3.1 U40.30(REG_OUT)
NetR147_2: R147.2 U40.27(RXCLK_PHYAD1)
NetR148_2: R148.2 U40.26(RXCTL_PHYAD2)
NetR149_2: R149.2 U40.25(RXD0_RXDLY)
NetR150_2: R150.2 U40.24(RXD1_TXDLY)
NetR151_2: R151.2 U40.23(RXD2_PLLOFF)
NetR152_2: R152.2 U40.22(RXD3_PHYAD0)
NetR163_2: R163.2 U40.20(TXCLK)
NetR166_2: R166.2 U40.19(TXCTL)
NetR169_2: R169.2 U40.18(TXD0)
NetR175_2: R175.2 U40.17(TXD1)
NetR180_2: R180.2 U40.16(TXD2)
NetR184_2: R184.2 U40.36(XTAL_IN)
NetR187_2: R187.2 U40.15(TXD3)
NetR190_2: R190.2 R198.2 U40.37(XTAL_OUT_EXT_CLK)
NetR201_1: R201.1 U40.39(RSET)
NetTP31_1: TP31.1 U40.35(CLKOUT)

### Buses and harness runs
bus ETH3.RXD[0..3]
bus ETH3.TXD[0..3]

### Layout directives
differential pair: RJ453_D1_N, RJ453_D1_P, RJ453_D2_N, RJ453_D2_P, RJ453_D3_N, RJ453_D3_P, RJ453_D4_N, RJ453_D4_P

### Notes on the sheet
- RGMII ETH3
- PHY_INTN
- TX_EN
- RX_DV
- TXC / RXC : no 2ns delay
  PHY Address :
  AD[2:0] : 101 (0x05) default
- RGMII power source :3V3
- Trace length <0.5 cm.
- (near U40) 22 ohms to place near MPU
- (near LE3) Trace length <0.5 cm.

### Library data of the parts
C106-C108 C125 C144 C154 C291 C292 C304 C307 C312 C315 C318 C319 = MCD-00006: as C105 on sheet Ethernet1
C113 C122 C278 C286 C300 C330 = MCD-00100: as C112 on sheet Ethernet1
C136 C139 = MCD-00015: as C135 on sheet Ethernet1
CN18 = MCD-01129: as CN17 on sheet Ethernet1
L11 L13 = MCD-00094: as L10 on sheet Ethernet1
LD9 = MCD-02901: as LD8 on sheet Ethernet1
LE3 = MCD-00048: as LE2 on sheet Ethernet1
R119-R124 R160 R297-R299 R306 R307 R315 R320 = MCD-00065: as R108 on sheet Ethernet1
R128 = MCD-00441: as R127 on sheet Ethernet1
R147-R152 R163 R166 R169 R175 R180 R187 R198 = MCD-02978: as R141-R146 on sheet Ethernet1
R184 R190 = MCD-00052: as R93 on sheet Ethernet1
R193 R203 R314 = MCD-00068: as R192 on sheet Ethernet1
R201 = MCD-00183: as R200 on sheet Ethernet1
R237 R238 = MCD-00064: as R235 on sheet Ethernet1
R308 R311 = MCD-00056: as R309 on sheet Ethernet1
TP31 = MCD-00074: Test Point 1mm; Part_Type: Misc; Part_Preference: Recommended; Initial_Board_Reference: MB1274; Component_Country_Of_Origin: Unknown; ID: 2518; ShowFields: YES
U40 = MCD-01130: as U39 on sheet Ethernet1
X6 = MCD-01463: as X5 on sheet Ethernet1

## Sheet Peripherals.SchDoc: Peripherals
size A3; Date: 01-DEC-2013; CompanyName: STMicroelectronics; Organization: Microcontrollers Division; Address1: 12, Rue Jules HOROWITZ; Address2: 38019 Grenoble; Address3: FRANCE; DocumentNumber: MB1272; Revision: A-01; SheetNumber: 17; SheetTotal: 18; Project: STM32MP15-DISCO PI
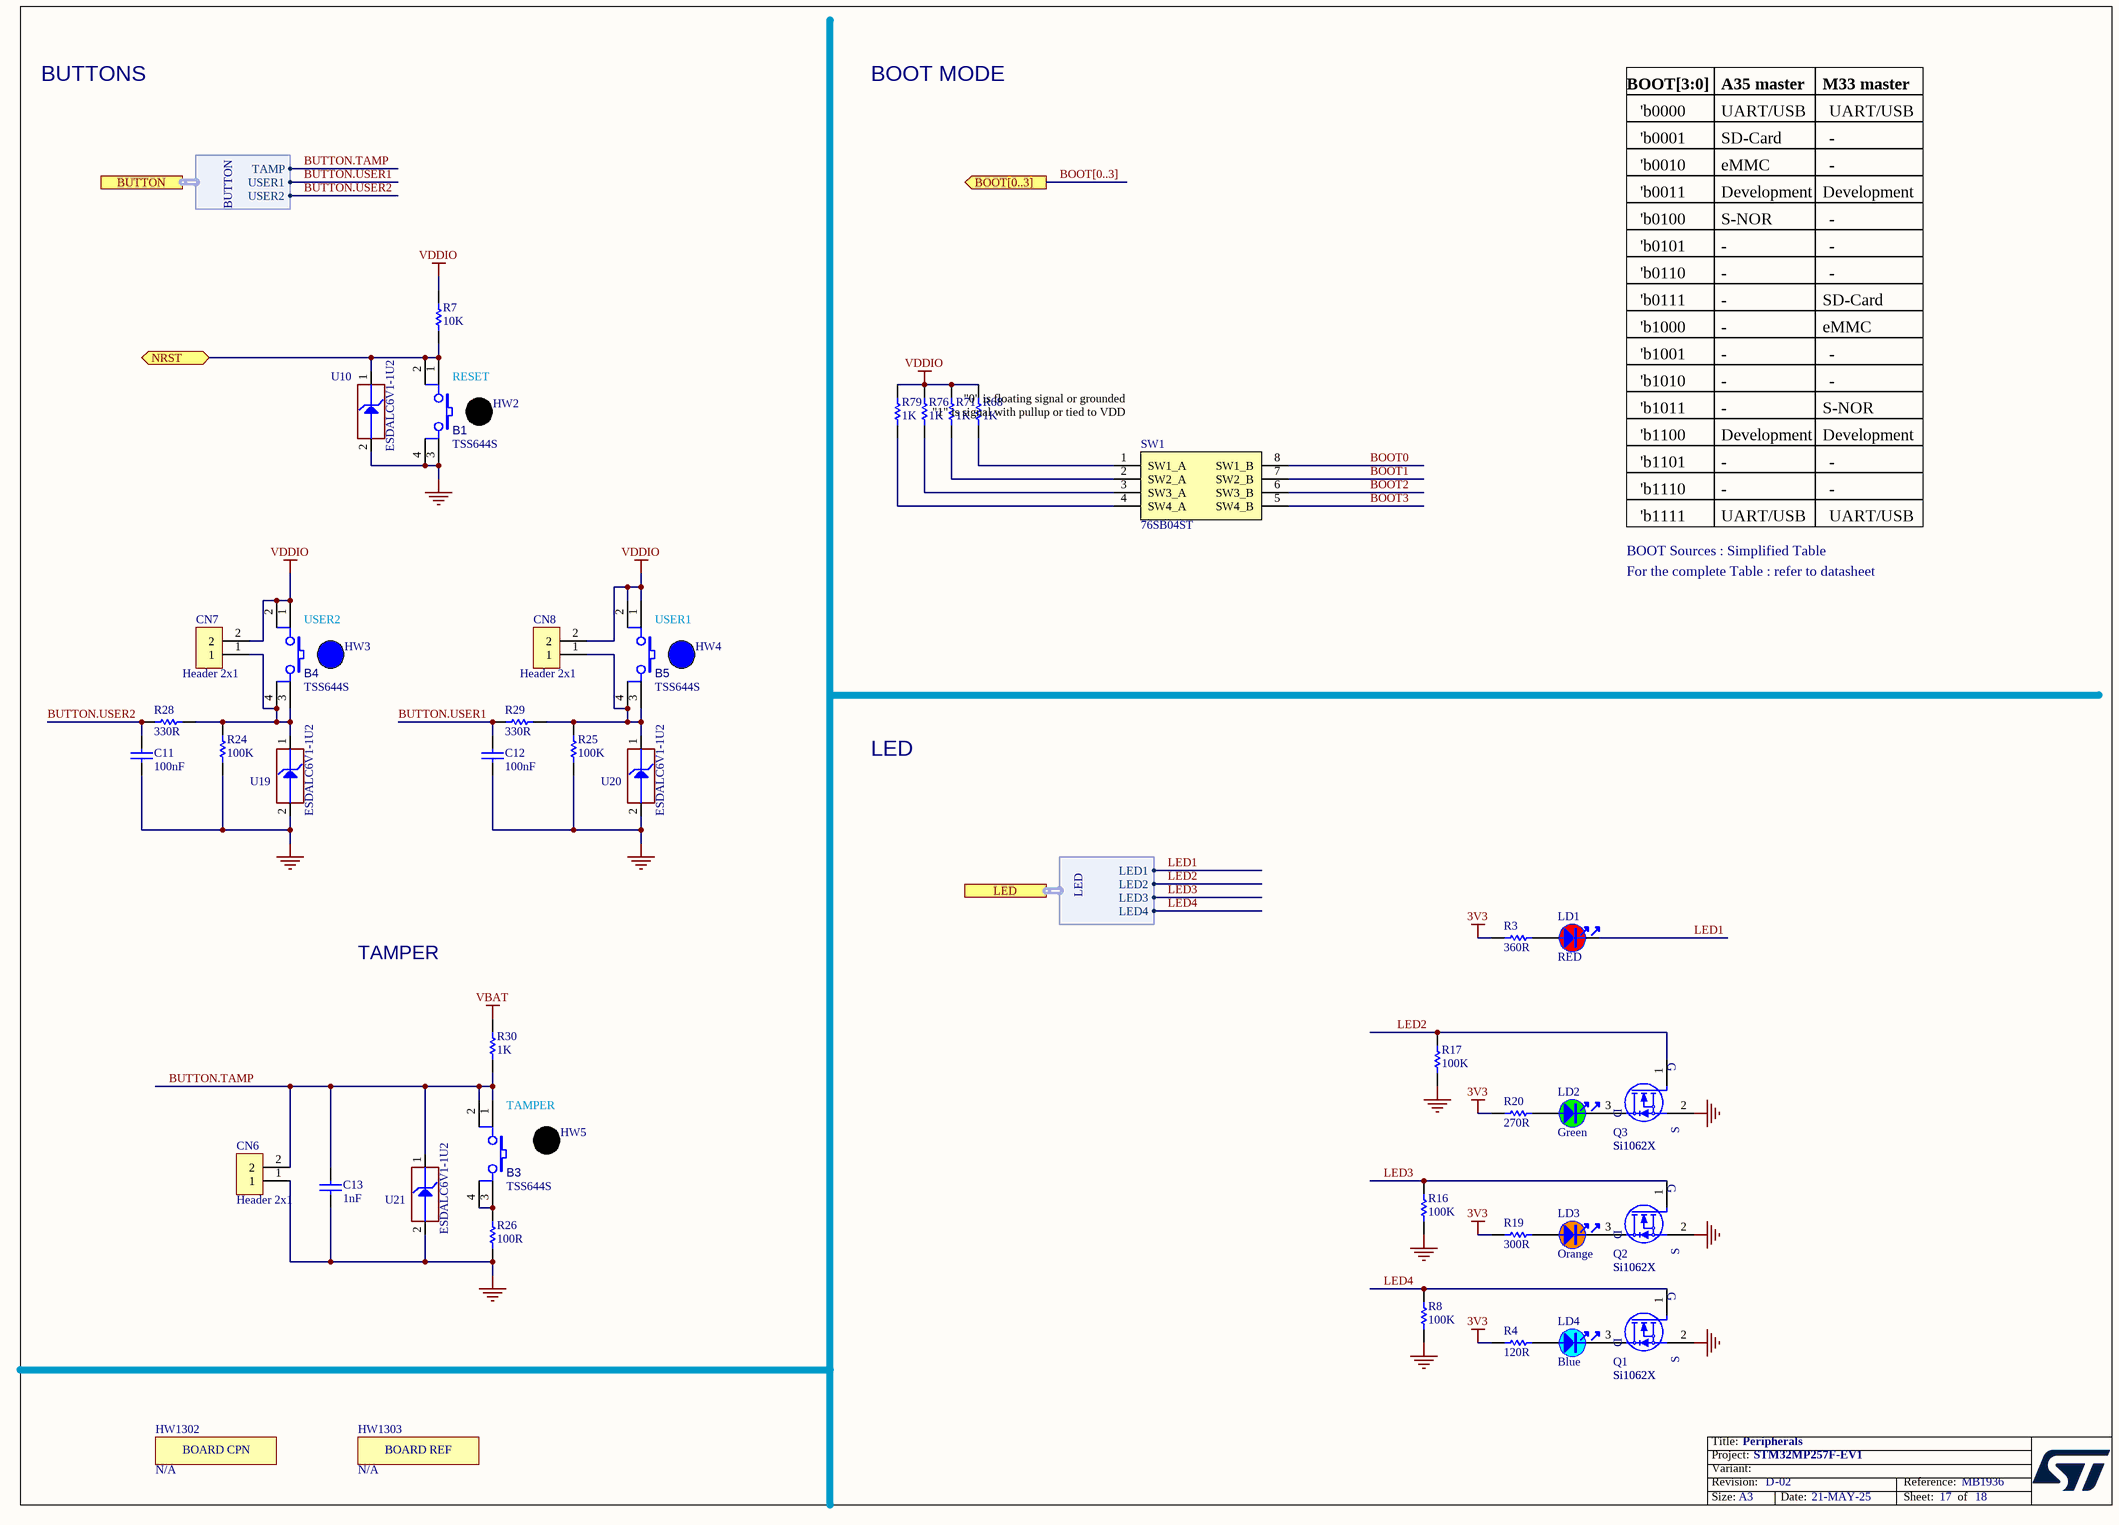
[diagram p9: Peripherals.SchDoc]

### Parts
B1  value TSS644S  [SWI_KNITTER_TSS644S]  (hidden comment: SW_PUSH_SMD)
B3  value TSS644S  [SWI_KNITTER_TSS644S]  (hidden comment: SW_PUSH_SMD)
B4  value TSS644S  [SWI_KNITTER_TSS644S]  (hidden comment: SW_PUSH_SMD)
B5  value TSS644S  [SWI_KNITTER_TSS644S]  (hidden comment: SW_PUSH_SMD)
C11  value 100nF  [C0402]  (hidden comment: Capacitor)
C12  value 100nF  [C0402]  (hidden comment: Capacitor)
C13  value 1nF  [C0402]  (hidden comment: Capacitor)
CN6  Header 2x1  [CON_SAMTEC_TSW-102-07-G-S]
CN7  Header 2x1  [CON_SAMTEC_TSW-102-07-G-S]
CN8  Header 2x1  [CON_SAMTEC_TSW-102-07-G-S]
HW2  SW-CAP-KTSC-62K  (value not drawn)  (mechanical)
HW3  AKTSC62B  (value not drawn)  (mechanical)
HW4  AKTSC62B  (value not drawn)  (mechanical)
HW5  SW-CAP-KTSC-62K  (value not drawn)  (mechanical)
HW1302  ​PCH W35 footprint requested to have a space on board for stickers.  [STICKER_BOARD-CPN_25X5]  (value not drawn)  (mechanical)
HW1303  STICKER_BOARD_REF  [STICKER_BOARD-REF_25X5]  (value not drawn)  (mechanical)
LD1  value RED  [LED_0603_VISHAY_VLMS1300-GS08_RED_1A2K_H0P8]  (hidden comment: LED_red)
LD2  value Green  [LED_0603_OSRAM_LG-Q396-PS-35_GREEN_1A2K_H0P4]  (hidden comment: LED_green)
LD3  value Orange  [LED_0603_VISHAY_VLMO1300-GS08_ORANGE_1A2K_H0P8]  (hidden comment: LED_orange)
LD4  value Blue  [LED_0603_SMD-B_BLUE_H0P4]  (hidden comment: LED_blue)
Q1  value Si1062X  Manufacturer_Part_Number: Si1062X  [MOS_SC89-3L]  (hidden comment: MOSFET_N-CHANNEL)
Q2  value Si1062X  Manufacturer_Part_Number: Si1062X  [MOS_SC89-3L]  (hidden comment: MOSFET_N-CHANNEL)
Q3  value Si1062X  Manufacturer_Part_Number: Si1062X  [MOS_SC89-3L]  (hidden comment: MOSFET_N-CHANNEL)
R3  value 360R  [R0402]  (hidden comment: Resistor)
R4  value 120R  [R0402]
R7  value 10K  [R0402]  (hidden comment: Resistor)
R8  value 100K  [R0402]  (hidden comment: Resistor)
R16  value 100K  [R0402]  (hidden comment: Resistor)
R17  value 100K  [R0402]  (hidden comment: Resistor)
R19  value 300R  [R0402]  (hidden comment: Resistor)
R20  value 270R  [R0402]  (hidden comment: Resistor)
R24  value 100K  [R0402]  (hidden comment: Resistor)
R25  value 100K  [R0402]  (hidden comment: Resistor)
R26  value 100R  [R0402]  (hidden comment: Resistor)
R28  value 330R  [R0402]  (hidden comment: Resistor)
R29  value 330R  [R0402]  (hidden comment: Resistor)
R30  value 1K  [R0402]  (hidden comment: Resistor)
R68  value 1K  [R0402]  (hidden comment: Resistor)
R71  value 1K  [R0402]  (hidden comment: Resistor)
R76  value 1K  [R0402]  (hidden comment: Resistor)
R79  value 1K  [R0402]  (hidden comment: Resistor)
SW1  76SB04ST  [SWI_GRAYHILL-INC_76SB04ST]
U10  value ESDALC6V1-1U2  [ESD_ST0201]  (hidden comment: ESD-TRANSIL)
U19  value ESDALC6V1-1U2  [ESD_ST0201]  (hidden comment: ESD-TRANSIL)
U20  value ESDALC6V1-1U2  [ESD_ST0201]  (hidden comment: ESD-TRANSIL)
U21  value ESDALC6V1-1U2  [ESD_ST0201]  (hidden comment: ESD-TRANSIL)

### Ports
BOOT[0..3] (out), BUTTON (harness BUTTON), LED (harness LED), NRST (bidir)

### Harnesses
BUTTON: TAMP, USER1, USER2
LED: LED1, LED2, LED3, LED4

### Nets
3V3: R3.1 R4.1 R19.2 R20.2
GND: B1.3 B1.4 C11.1 C12.1 C13.1 CN6.1 Q1.2(S) Q2.2(S) Q3.2(S) R8.1 R16.1 R17.1 R24.1 R25.1 R26.2 U10.2(GND) U19.2(GND) U20.2(GND) U21.2(GND)
VBAT: R30.2
VDDIO: B4.1 B4.2 B5.1 B5.2 CN7.2 CN8.2 R7.2 R68.2 R71.2 R76.2 R79.2
BOOT0: SW1.8(SW1_B)
BOOT1: SW1.7(SW2_B)
BOOT2: SW1.6(SW3_B)
BOOT3: SW1.5(SW4_B)
BUTTON.TAMP: B3.1 B3.2 C13.2 CN6.2 R30.1 U21.1(IO1) ; port BUTTON.TAMP
BUTTON.User1: C12.2 R29.1 ; port BUTTON.USER1
BUTTON.User2: C11.2 R28.1 ; port BUTTON.USER2
LED1: LD1.2 ; port LED.LED1
LED2: Q3.1(G) R17.2 ; port LED.LED2
LED3: Q2.1(G) R16.2 ; port LED.LED3
LED4: Q1.1(G) R8.2 ; port LED.LED4
NRST: B1.1 B1.2 R7.1 U10.1(IO1) ; port NRST
NetB3_3: B3.3 B3.4 R26.1
NetB4_3: B4.3 B4.4 CN7.1 R24.2 R28.2 U19.1(IO1)
NetB5_3: B5.3 B5.4 CN8.1 R25.2 R29.2 U20.1(IO1)
NetLD1_1: LD1.1 R3.2
NetLD2_1: LD2.1 R20.1
NetLD2_2: LD2.2 Q3.3(D)
NetLD3_1: LD3.1 R19.1
NetLD3_2: LD3.2 Q2.3(D)
NetLD4_1: LD4.1 R4.2
NetLD4_2: LD4.2 Q1.3(D)
NetR68_1: R68.1 SW1.1(SW1_A)
NetR71_1: R71.1 SW1.2(SW2_A)
NetR76_1: R76.1 SW1.3(SW3_A)
NetR79_1: R79.1 SW1.4(SW4_A)

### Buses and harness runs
bus BOOT[0..3] = port BOOT[0..3]

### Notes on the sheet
- BUTTONS
- BOOT MODE
- BOOT[3:0]
- A35 master
- M33 master
- 'b0001
- 'b0000
- 'b0010
- UART/USB
- SD-Card
- eMMC
- -
- 'b0011
- 'b0100
- Development
- S-NOR
- 'b0101
- 'b0110
- 'b0111
- (near B1) RESET
- 'b1000
- 'b1001
- "0" is floating signal or grounded
- (near SW1) "1" is signal with pullup or tied to VDD
- 'b1010
- 'b1011
- 'b1100
- 'b1101
- 'b1110
- BOOT Sources : Simplified Table
- For the complete Table : refer to datasheet
- 'b1111
- USER2
- USER1
- LED
- TAMPER
- (near B3) TAMPER

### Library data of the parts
B1 B4 B5 = MCD-02417: Push Button, NO, 0.05A, 12V, 2.6N, SMD, 9.0x6.2mm, T=7.3mm, changeable caps KTSC-6xx; Manufacturer: KNITTER-SWITCH; Part_Type: Misc; Part_Preference: Recommended; Manufacturer_HQ_COO: Unknown; Component_Country_Of_Origin: China; ID: 4523; ShowFields: YES
B3 = MCD-02417: Push Button, NO, 0.05A, 12V, 2.6N, SMD, 9.0x6.2mm, T=7.3mm, changeable caps KTSC-6xx; Part_Type: Misc; Manufacturer: KNITTER-SWITCH; Part_Preference: Recommended; Manufacturer_HQ_COO: Unknown; Component_Country_Of_Origin: China; ShowFields: YES; ID: 4523
C11 C12 = MCD-00006: Capacitor, MLCC, 100nF, 16V, X7R, +/-10%, 0402, T=0.5mm; Manufacturer_Part_Number: CC0402KRX7R7BB104; Manufacturer: YAGEO; Part_Preference: Recommended; Alternate_Manufacturer: MURATA; Alternate_Manufacturer_Part_Number: GCM155R71C104KA55D; Partial_Alternate_Internal_Part_Number: MCD-03299; Order_Code_RS: 9402047; Component_Country_Of_Origin: China; ID: 2474; ShowFields: YES
C13 = MCD-00198: Capacitor, MLCC, 1nF, 16V, X7R, +/-10%, 0402, T=0.5mm; Part_Preference: Recommended; Manufacturer: YAGEO; Manufacturer_Part_Number: CC0402KRX7R7BB102; Component_Country_Of_Origin: China; ShowFields: YES; ID: 2665
CN6-CN8 = MCD-00032: Header, 2x1, 2,54mm, VR, TH, Height 5.84mm/2.54mm; Part_Type: Connector; Part_Preference: Recommended; Manufacturer: SAMTEC; Manufacturer_Part_Number: TSW-102-07-G-S; Alternate_Manufacturer: JIUBABA; Alternate_Manufacturer_Part_Number: 313102S111116; Partial_Alternate_Internal_Part_Number: MCD-03979; Component_Country_Of_Origin: China, Costa Rica, Malaysia, USA, Vietnam; Order_Code_RS: 2505044; ID: 2484; ShowFields: YES
HW2 HW5 = MCD-02420: Black round cap for TSS6x series; Part_Type: Mechanical; Part_Preference: Recommended; Manufacturer: KNITTER-SWITCH; Manufacturer_HQ_COO: Unknown; Partial_Alternate_Internal_Part_Number: MCD-02526; Component_Country_Of_Origin: China; ID: 4526; ShowFields: YES; Alternate_EMS: M
HW3 HW4 = MCD-02136: Switch hat, blue, For KTSC-62B; Part_Type: Mechanical; Part_Preference: Recommended; Manufacturer: APEM; Alternate_Manufacturer: KNITTER-SWITCH; Partial_Alternate_Internal_Part_Number: MCD-02419; Order_Code_RS: 378-6779; Component_Country_Of_Origin: Unknown; ID: 4236; ShowFields: YES
HW1302 = MCD-00547: Sticker to mention board CPN code; Part_Type: Misc; Part_Preference: Recommended; Provided_By: SUBCO; Initial_Board_Reference: MB1319; ID: 3197; ShowFields: YES; Component_Country_Of_Origin: Unknown
HW1303 = MCD-00235: Sticker to mention board reference + serial number; Part_Type: Misc; Part_Preference: Recommended; Provided_By: SUBCO; Initial_Board_Reference: MB1319; ID: 2632; ShowFields: YES; Component_Country_Of_Origin: Unknown
LD1 = MCD-00587: LED Red, 0603 SMD, 2V Forward Voltage; Part_Type: Display; Manufacturer_Part_Number: VLMS1300-GS08; Manufacturer: VISHAY; Alternate_Manufacturer_Part_Number: LS Q976-NR-1; Alternate_Manufacturer: OSRAM OPTO SEMICONDUCTORS; Alternate_Internal_Part_Number: MCD-02401; Part_Preference: Recommended; Partial_Alternate_Internal_Part_Number: MCD-03983; Provided_By: SUBCO; Component_Country_Of_Origin: China; ID: 3154; ShowFields: YES
LD2 = MCD-02901: as LD8 on sheet Ethernet1
LD3 = MCD-00591: LED, Orange, 2V, 20mA, 0603; Part_Type: Display; Part_Preference: Recommended; Manufacturer: VISHAY; Manufacturer_Part_Number: VLMO1300-GS08; Order_Code_RS: 7730446; Component_Country_Of_Origin: China; ShowFields: YES; ID: 3153
LD4 = MCD-02786: LED, Blue, 2.5V to 3.1V, 10mA, 0603; Part_Type: Display; Part_Preference: Recommended; Manufacturer: EVERLIGHT; Manufacturer_Part_Number: 19-217/BHC-ZL1M2RY/6T; Full_Alternate_Internal_Part_Number: MCD-01131; Component_Country_Of_Origin: China; ShowFields: YES; ID: 4898
Q1-Q3 = MCD-02221: MOSFET N-CH 20V SC-89; Part_Preference: Recommended; Part_Type: Transistor; Manufacturer: VISHAY; Order_Code_RS: 812-3044; Component_Country_Of_Origin: Philippines; ID: 4321; ShowFields: YES
R3 = MCD-00461: Resistor,360R,0402,1%,1/16W; Manufacturer_Part_Number: RC0402FR-07360RL; Manufacturer: YAGEO; Part_Preference: Recommended; Provided_By: SUBCO; ECCN_US: EAR99; ECCN_EU: NEC; Component_Country_Of_Origin: China; ID: 2816; ShowFields: YES
R4 = MCD-00194: Resistor,120R,0402,1%,1/16W; Manufacturer_Part_Number: RC0402FR-07120RL; Manufacturer: YAGEO; Part_Preference: Recommended; Provided_By: SUBCO; ECCN_US: EAR99; ECCN_EU: NEC; Component_Country_Of_Origin: China; ID: 2674; ShowFields: YES
R7 = MCD-00053: Resistor,10K,0402,1%,1/16W; Manufacturer_Part_Number: RC0402FR-0710KL; Manufacturer: YAGEO; BMS_Part_Number: 9131590; Part_Preference: Recommended; Order_Code_RS: 9239359; Component_Country_Of_Origin: China; ID: 2539; ShowFields: YES
R8 R16 R17 R24 R25 = MCD-00059: Resistor,100K,0402,1%,1/16W; Manufacturer_Part_Number: RC0402FR-07100KL; Manufacturer: YAGEO; Alternate_Manufacturer_Part_Number: RT0402FRE07100KL; Part_Preference: Recommended; Partial_Alternate_Internal_Part_Number: MCD-03301; Order_Code_RS: 2421891; Component_Country_Of_Origin: China; ID: 2533; ShowFields: YES
R19 = MCD-00449: Resistor,300R,0402,1%,1/16W; Manufacturer_Part_Number: RC0402FR-07300RL; Manufacturer: YAGEO; Part_Preference: Recommended; Provided_By: SUBCO; ECCN_US: EAR99; ECCN_EU: NEC; Component_Country_Of_Origin: China; ID: 2832; ShowFields: YES
R20 = MCD-00441: as R127 on sheet Ethernet1
R26 = MCD-00067: Resistor, 100R, 0402, +/- 1%, 1/16W; Manufacturer_Part_Number: RC0402FR-07100RL; Manufacturer: YAGEO; Part_Preference: Recommended; Order_Code_RS: 9239111; Component_Country_Of_Origin: China; ShowFields: YES; ID: 2527
R28 R29 = MCD-00062: Resistor,330R,0402,1%,1/16W; Manufacturer_Part_Number: RC0402FR-07330RL; Manufacturer: YAGEO; Part_Preference: Recommended; Order_Code_RS: 9239170; Component_Country_Of_Origin: China; ID: 2529; ShowFields: YES
R30 = MCD-00061: Resistor, 1K, 0402, +/-1%,1/16W; Manufacturer_Part_Number: RC0402FR-071KL; Manufacturer: YAGEO; Part_Preference: Recommended; Order_Code_RS: 9239235; Component_Country_Of_Origin: China; ShowFields: YES; ID: 2532
R68 R71 R76 R79 = MCD-00061: Resistor,1K,0402,1%,1/16W; Part_Preference: Recommended; Manufacturer: YAGEO; Manufacturer_Part_Number: RC0402FR-071KL; Order_Code_RS: 9239235; Component_Country_Of_Origin: China; ID: 2532; ShowFields: YES
SW1 = MCD-02256: Quad SPST switch, TH, 2.54mm pitch, height 7.5mm; Part_Preference: Recommended; Part_Type: Misc; Manufacturer: ECE; Alternate_Manufacturer: TE Connectivity; Alternate_Manufacturer_Part_Number: 5435640-2; Order_Code_RS: 878-0230; Component_Country_Of_Origin: China°°; ID: 4356; ShowFields: YES
U10 U19-U21 = MCD-00170: ESD protection 6V1; Part_Type: Diode; Manufacturer: STMICROELECTRONICS; BMS_Part_Number: 9151132; Part_Preference: Recommended; Manufacturer_HQ_COO: EU; Component_Country_Of_Origin: China; Order_Code_RS: 795-8404; ID: 2696; ShowFields: YES

## Sheet QSPI_NOR.SchDoc: QSPI_NOR
size A4; Date: Not used; ApprovedBy: Not used; CheckedBy: Not used; Author: Not used; CompanyName: STMicroelectronics; DrawnBy: Not used; Engineer: Not used; Organization: Not used; Address1: Not used; Address2: Not used; Address3: Not used; Address4: Not used; DocumentNumber: Not used; Revision: Not used; SheetNumber: 14; SheetTotal: 18
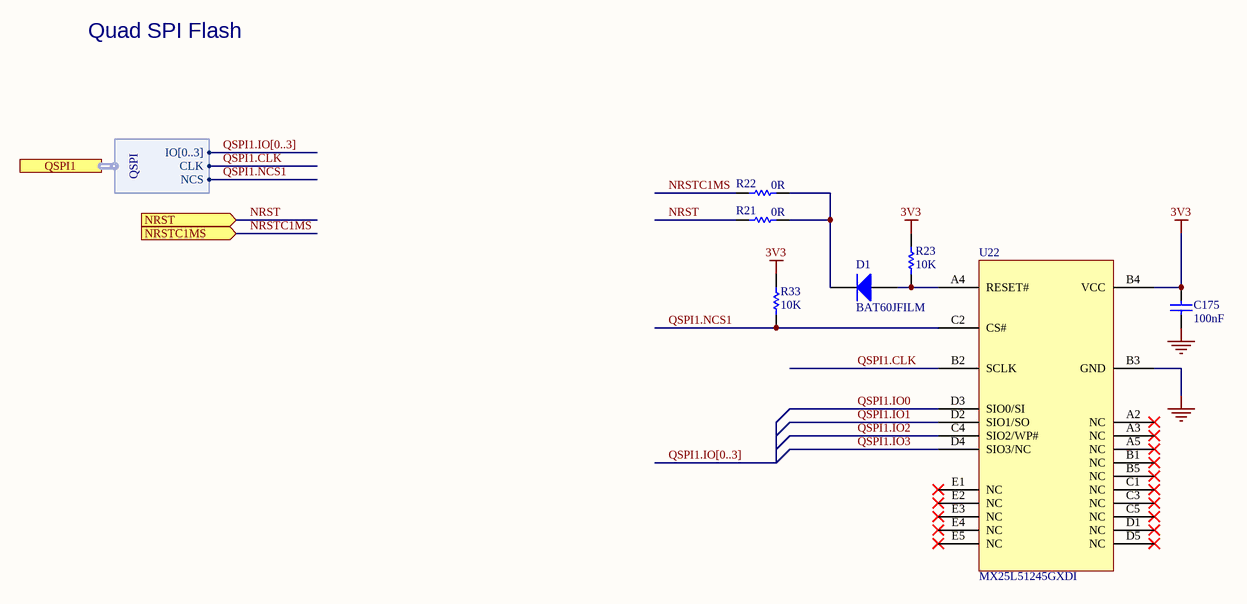
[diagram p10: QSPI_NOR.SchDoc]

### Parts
C175  value 100nF  [C0402]  (hidden comment: Capacitor)
D1  BAT60JFILM  [DIO_SOD323]
R21  value 0R  [R0402]  (hidden comment: Resistor)
R22  value 0R  [R0402]  (hidden comment: Resistor)
R23  value 10K  [R0402]  (hidden comment: Resistor)
R33  value 10K  [R0402]  (hidden comment: Resistor)
U22  value MX25L51245GXDI  [ICC_BGA24_5X5-BALL-ARRAY_6X8_P1]  (hidden comment: MX25L51245G)

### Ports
NRST (in), NRSTC1MS (in), QSPI1 (harness QSPI)

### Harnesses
QSPI: IO[0..3], CLK, NCS

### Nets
3V3: C175.2 R23.2 R33.2 U22.B4(VCC)
GND: C175.1 U22.B3(GND)
NRST: R21.1 ; port NRST
NRSTC1MS: R22.1 ; port NRSTC1MS
QSPI1.CLK: U22.B2(SCLK) ; port QSPI1.CLK
QSPI1.IO0: U22.D3(SIO0/SI)
QSPI1.IO1: U22.D2(SIO1/SO)
QSPI1.IO2: U22.C4(SIO2/WP#)
QSPI1.IO3: U22.D4(SIO3/NC)
QSPI1.NCS1: R33.1 U22.C2(CS#) ; port QSPI1.NCS
NetD1_1: D1.1(A) R23.1 U22.A4(RESET#)
NetD1_2: D1.2(K) R21.2 R22.2

Not connected (* = marked no-connect by the designer): U22 A2(NC)* A3(NC)* A5(NC)* B1(NC)* B5(NC)* C1(NC)* C3(NC)* C5(NC)* D1(NC)* D5(NC)* E1(NC)* E2(NC)* E3(NC)* E4(NC)* E5(NC)*

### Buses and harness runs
bus QSPI1.IO[0..3]

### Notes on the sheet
- Quad SPI Flash

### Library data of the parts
C175 = MCD-00006: as C14 on sheet FDCAN
D1 = MCD-00034: BMS_Part_Number: 9151097; Part_Type: Diode; Part_Preference: Recommended; Manufacturer: STMICROELECTRONICS; Manufacturer_HQ_COO: EU; Component_Country_Of_Origin: China; ShowFields: YES; ID: 2483; Order_Code_RS: 714-6879
R21 R22 = MCD-00052: Resistor,0R,0402,5%,1/16W; Manufacturer_Part_Number: RC0402JR-070RL; Manufacturer: YAGEO; Part_Preference: Recommended; Order_Code_RS: 9232516RL; Component_Country_Of_Origin: China; ID: 2540; ShowFields: YES
R23 R33 = MCD-00053: Resistor,10K,0402,1%,1/16W; Manufacturer_Part_Number: RC0402FR-0710KL; Manufacturer: YAGEO; BMS_Part_Number: 9131590; Part_Preference: Recommended; ECCN_US: EAR99; ECCN_EU: NEC; Provided_By: SUBCO; Order_Code_RS: 9239359; Component_Country_Of_Origin: China; ID: 2539; ShowFields: YES
U22 = MCD-00114: Memory,Serial-NOR,512Mb,3V; Part_Type: IC; Manufacturer: MACRONIX; Part_Preference: Recommended; ECCN_US: tbd; Provided_By: SUBCO; Component_Country_Of_Origin: Unknown; ID: 2753; ShowFields: YES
